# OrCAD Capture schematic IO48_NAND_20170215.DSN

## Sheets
1 01. Title: title: HPS IO48 NAND Daughter Card; rev: A1; note: 150-0330633-A1     (6XX-44480R)
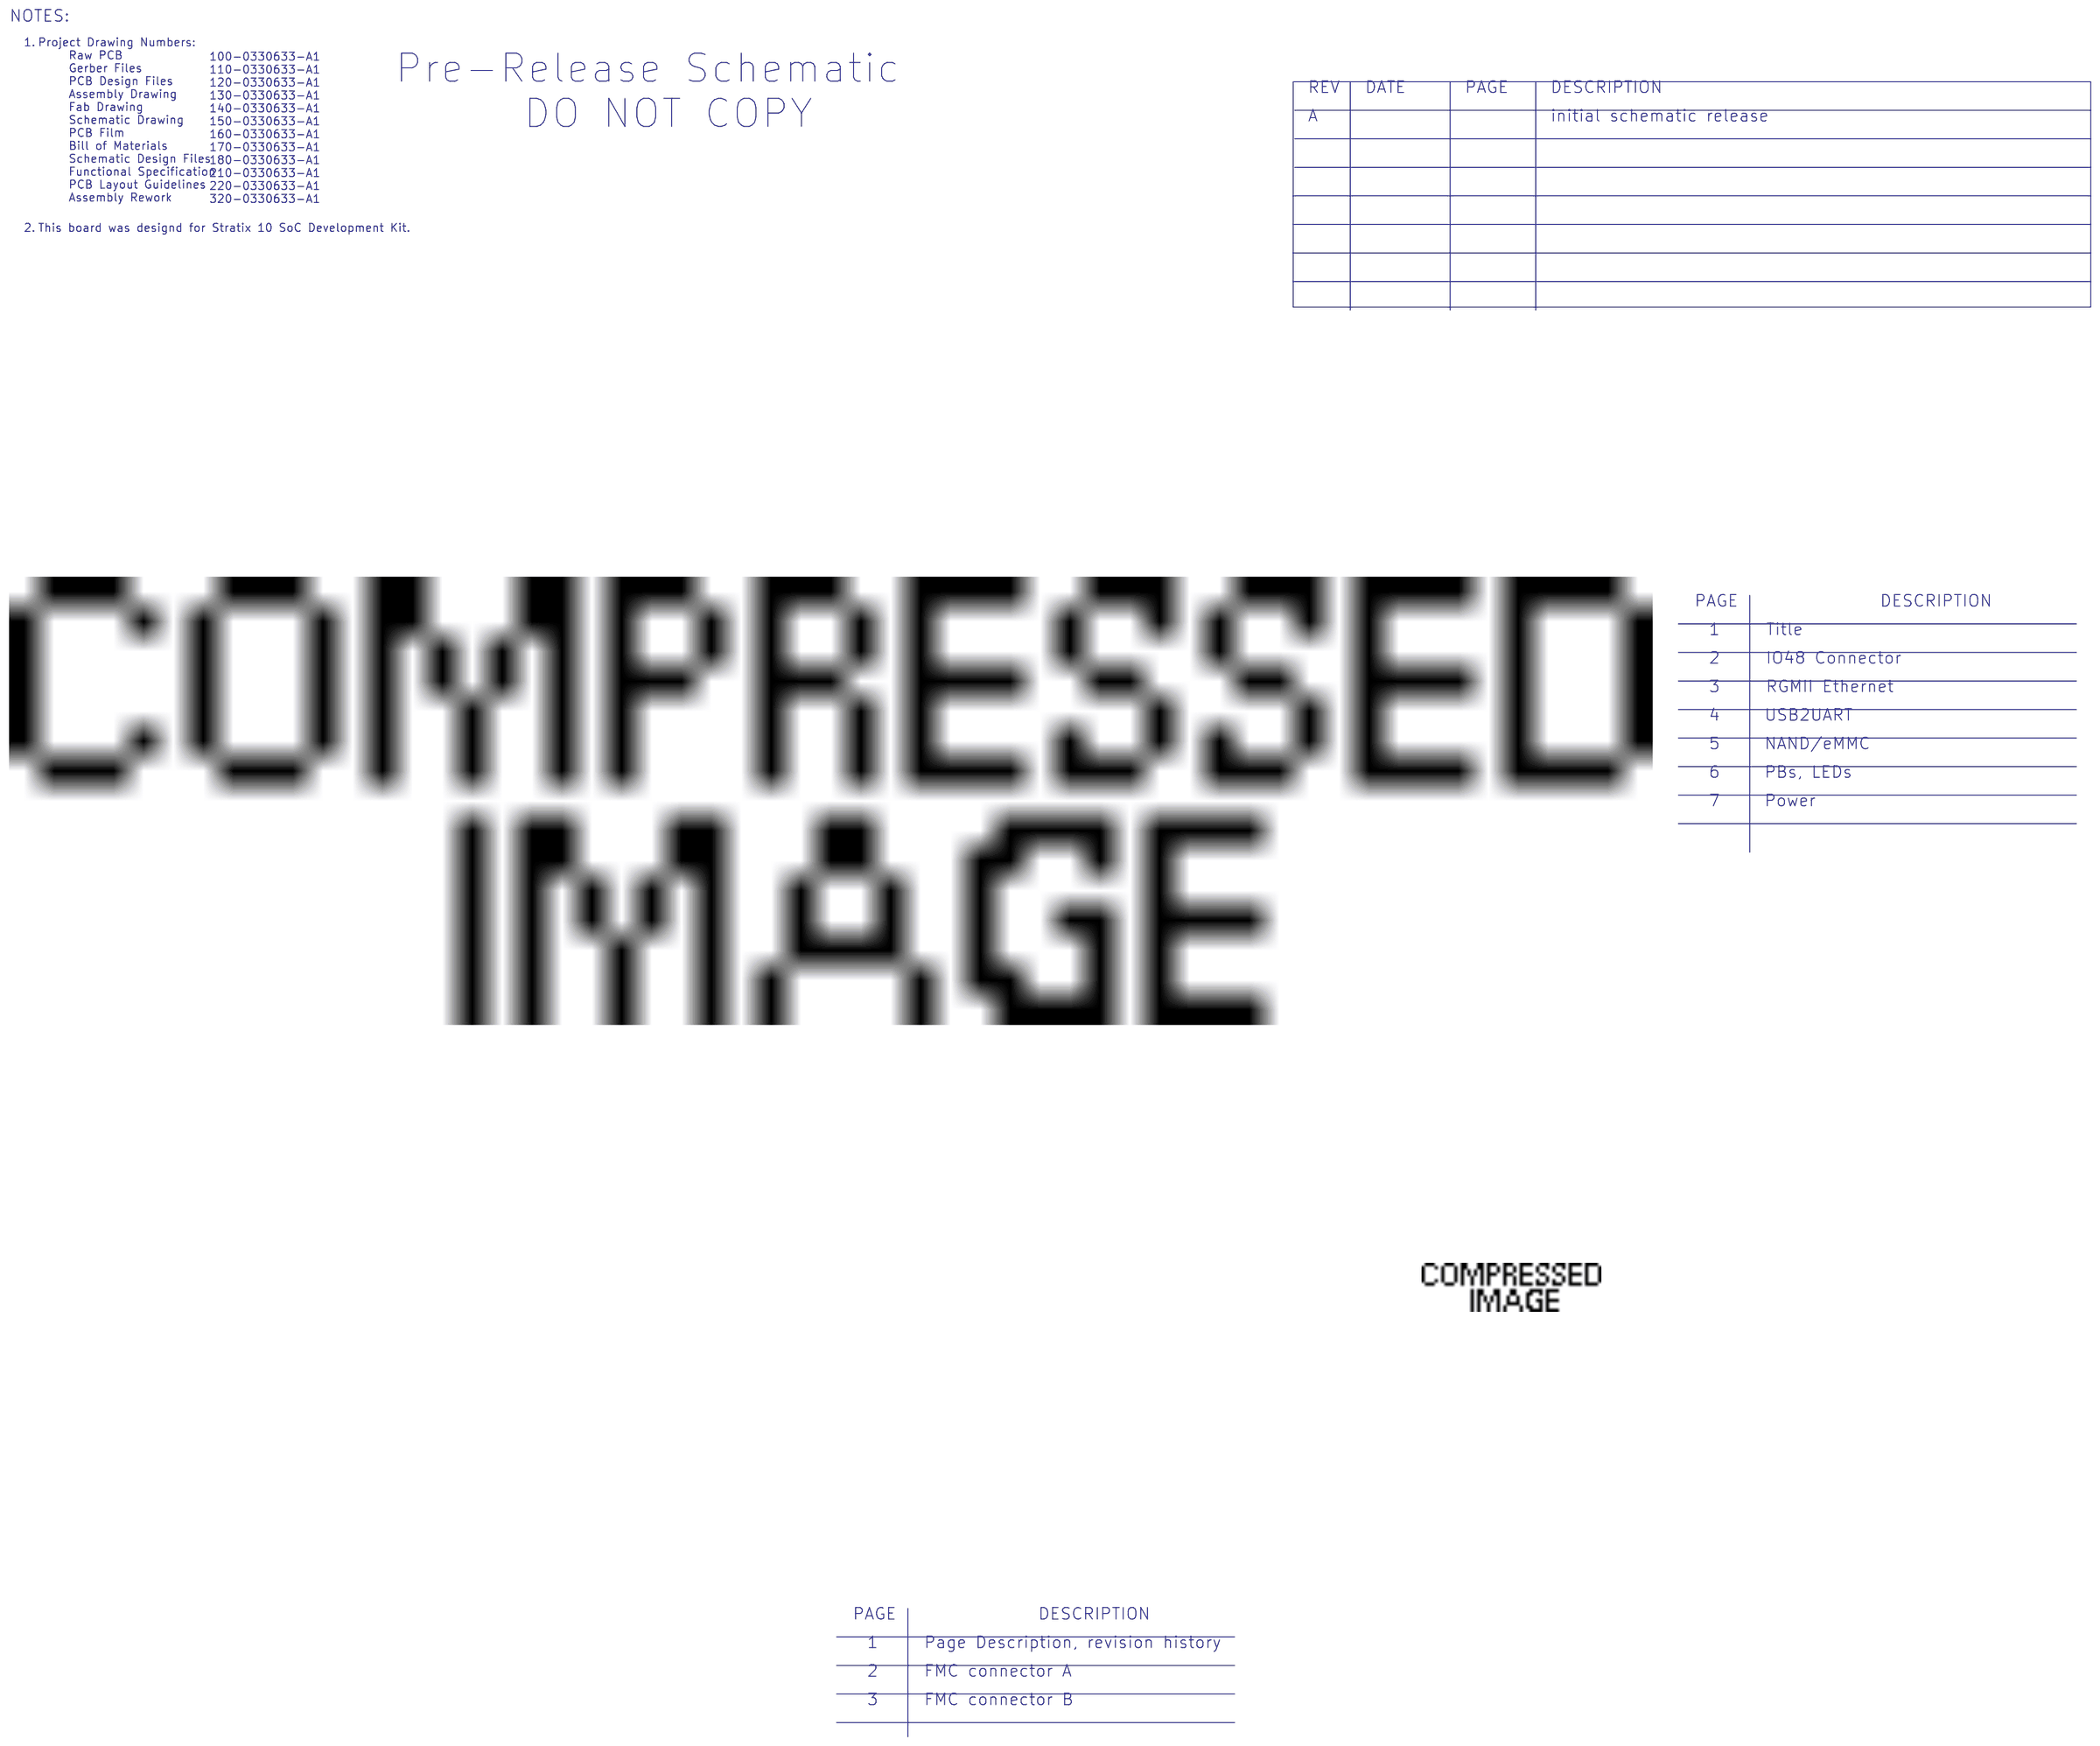
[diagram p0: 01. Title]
2 02. IO48 Connector: size B
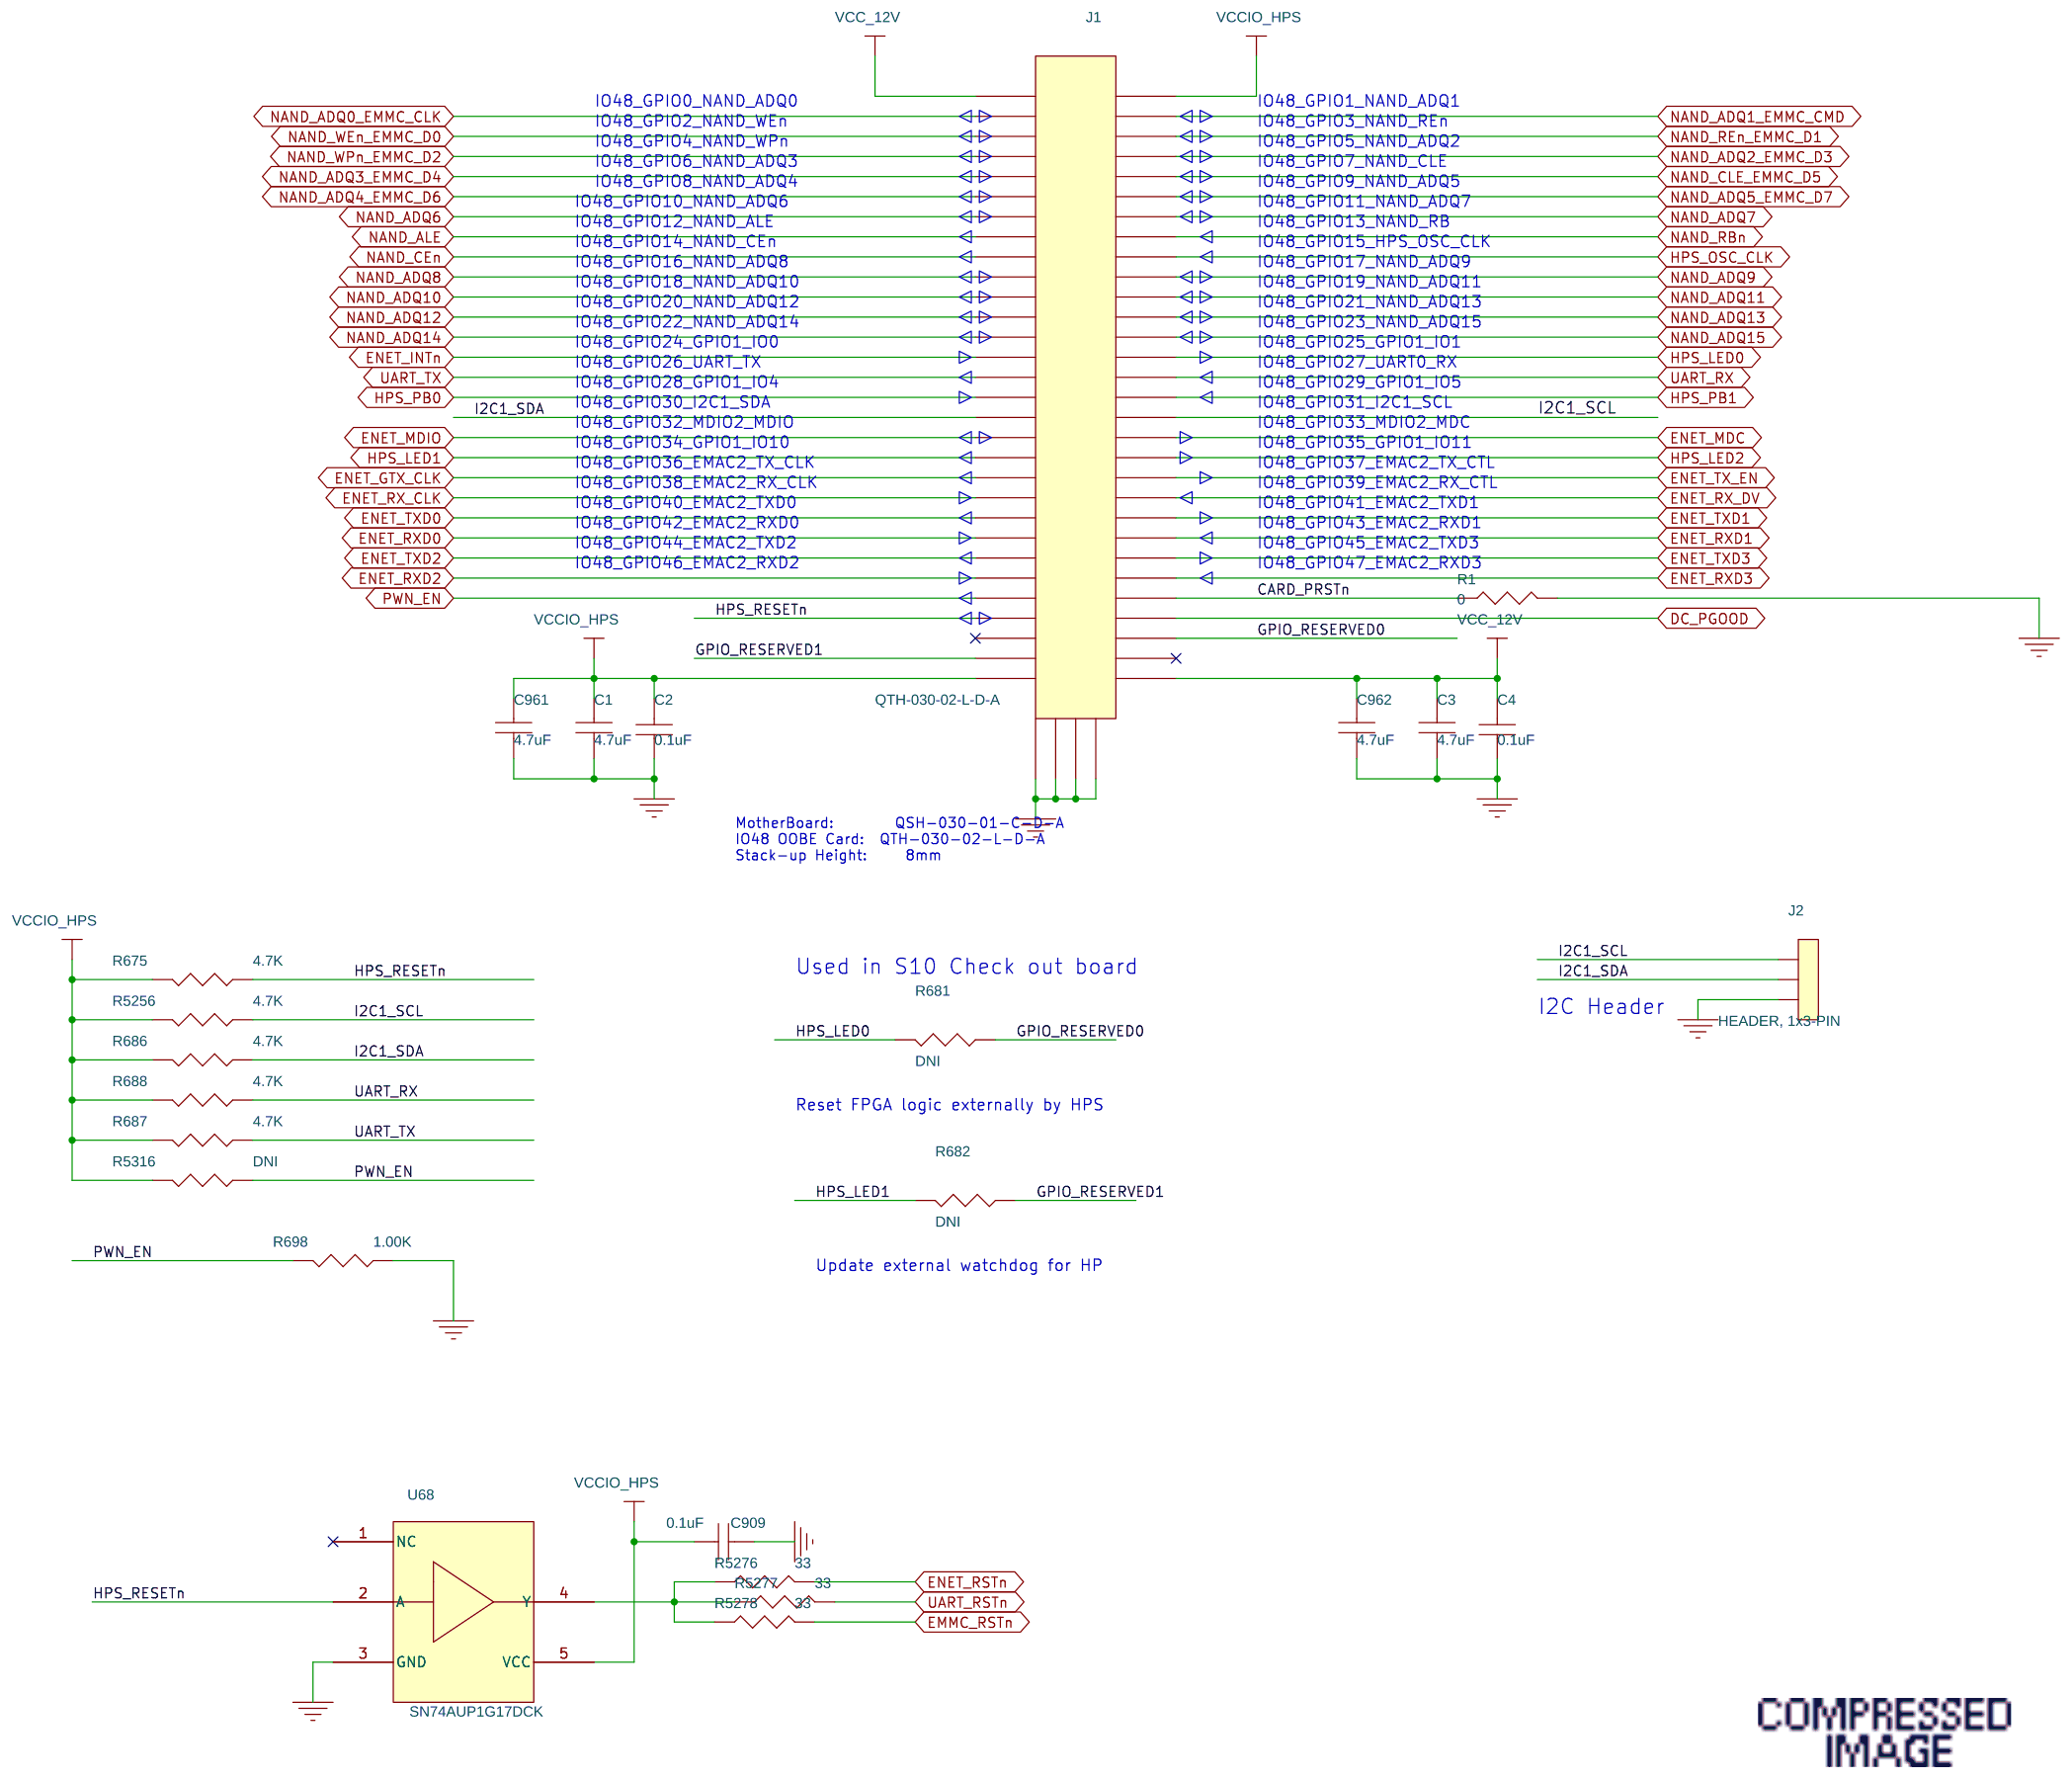
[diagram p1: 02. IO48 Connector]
3 03. RGMII Ethernet: size B
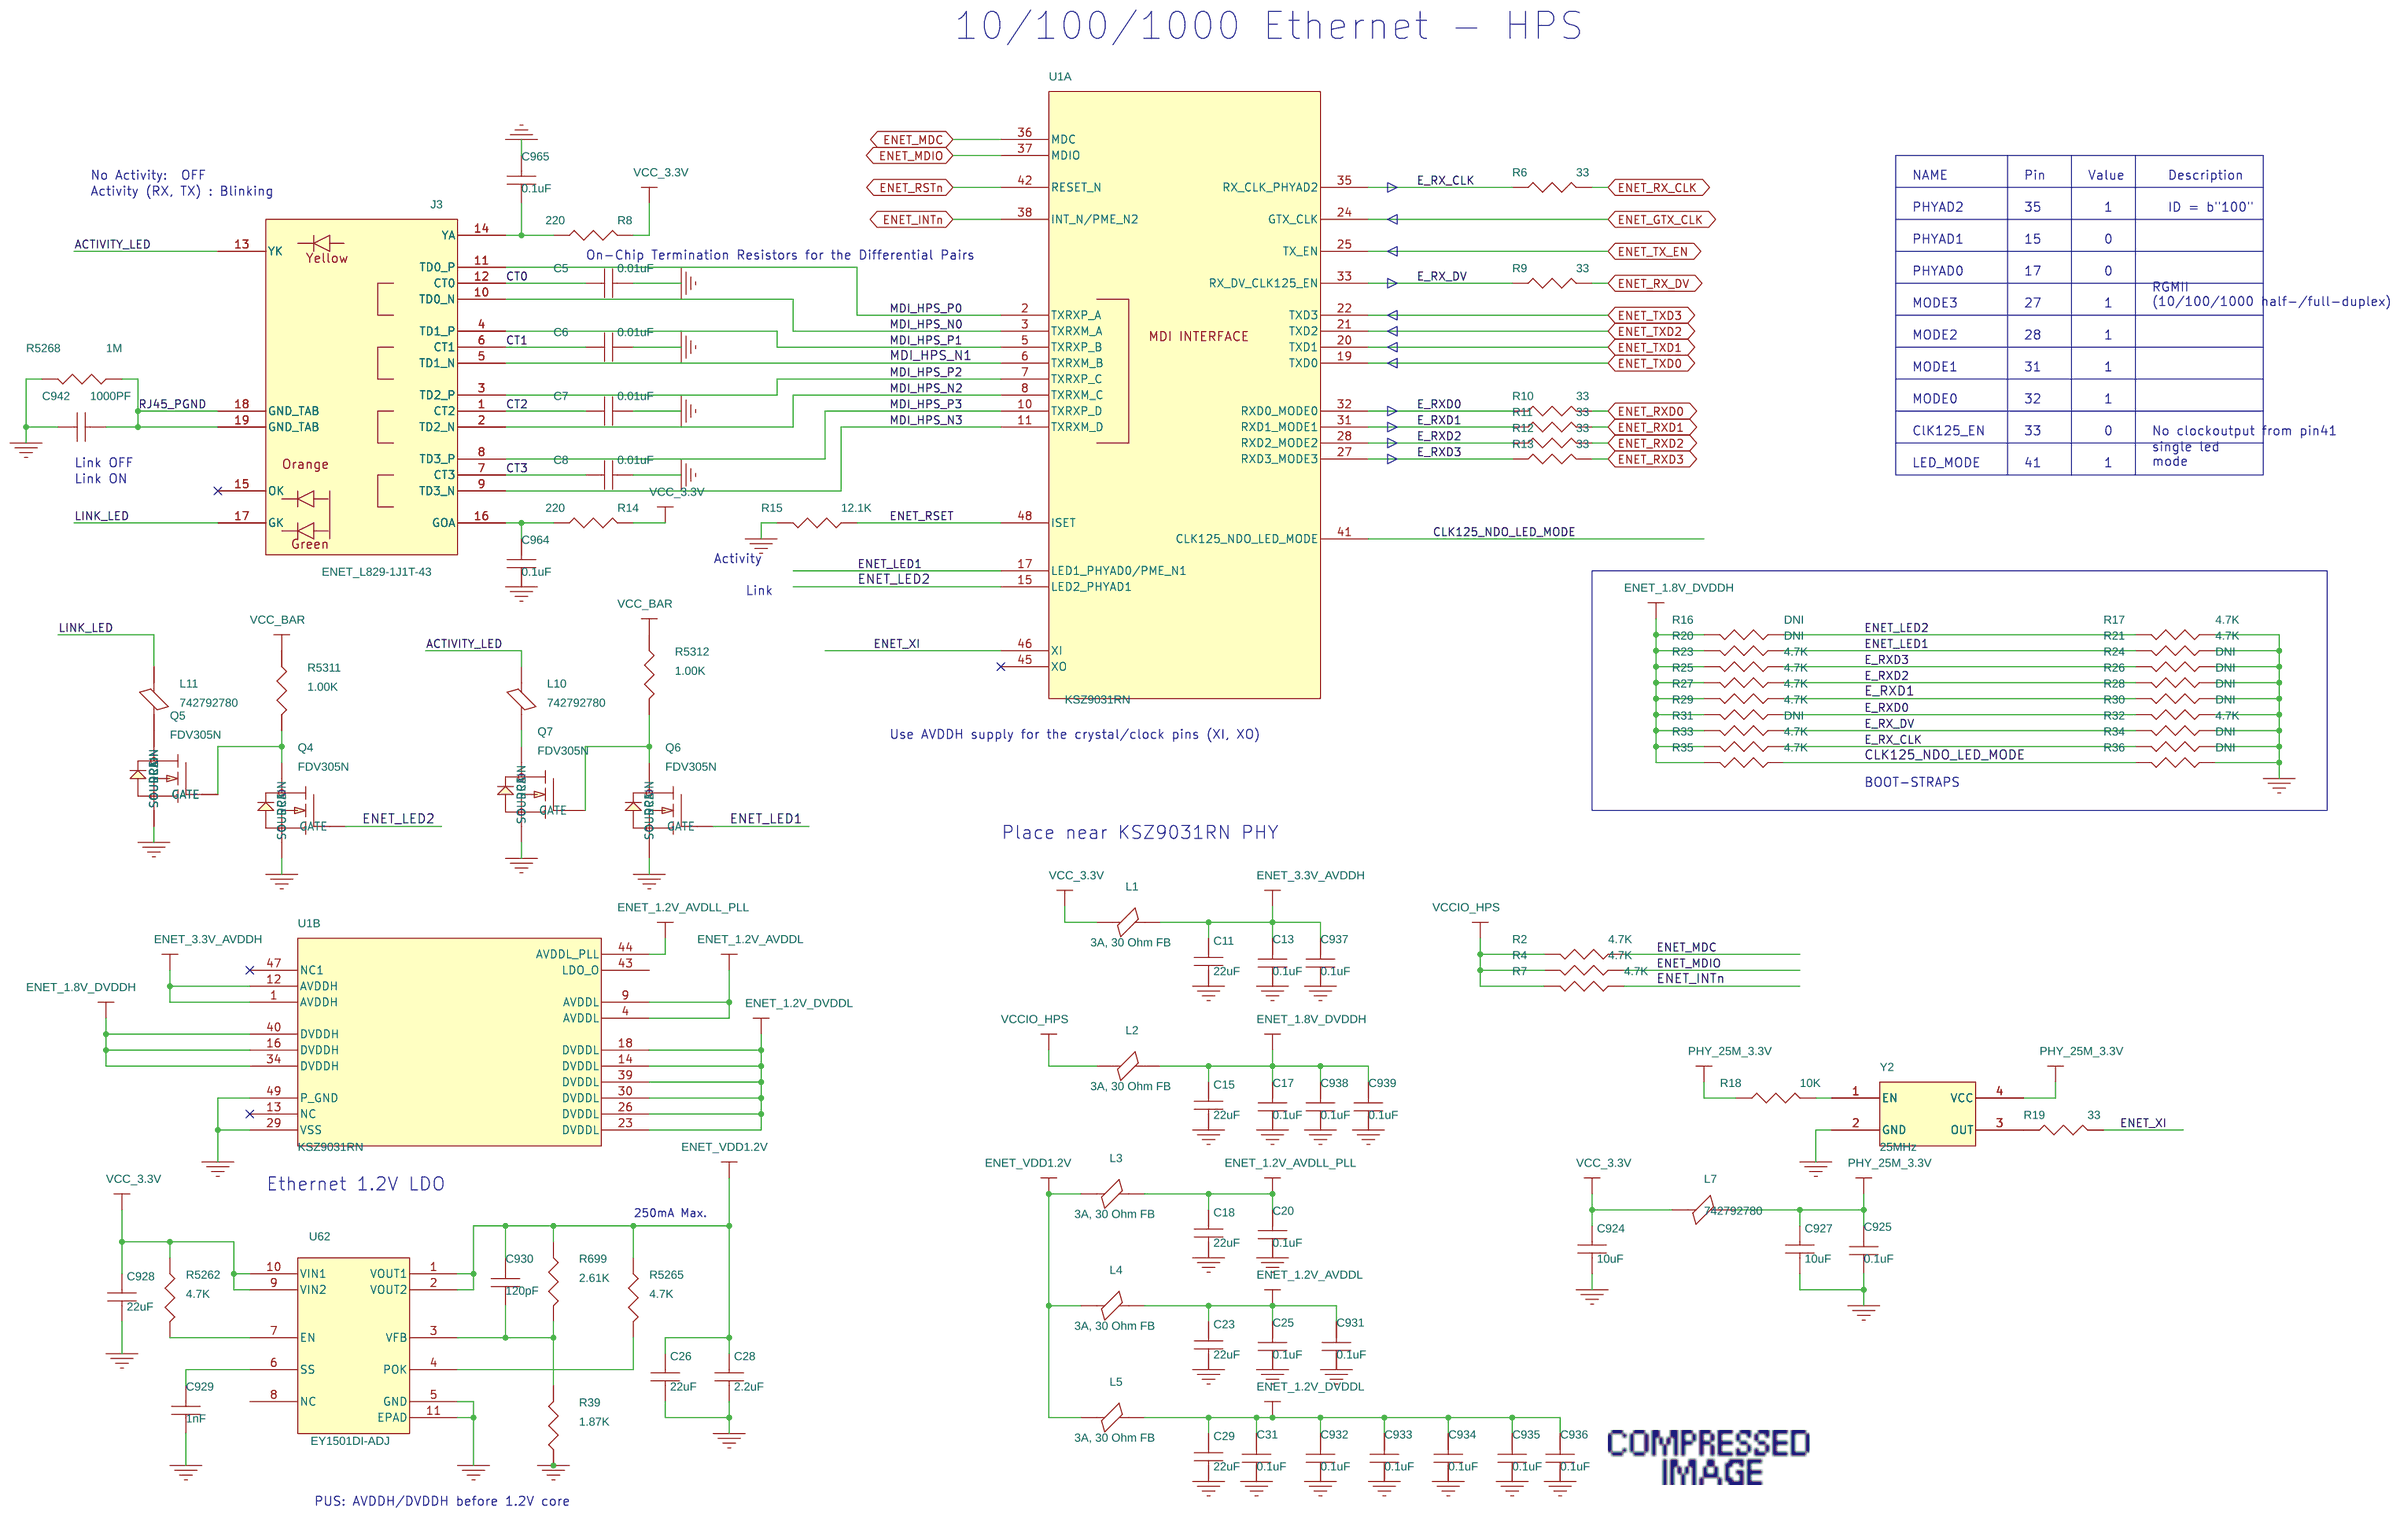
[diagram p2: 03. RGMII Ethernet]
4 04. USB2UART: size B
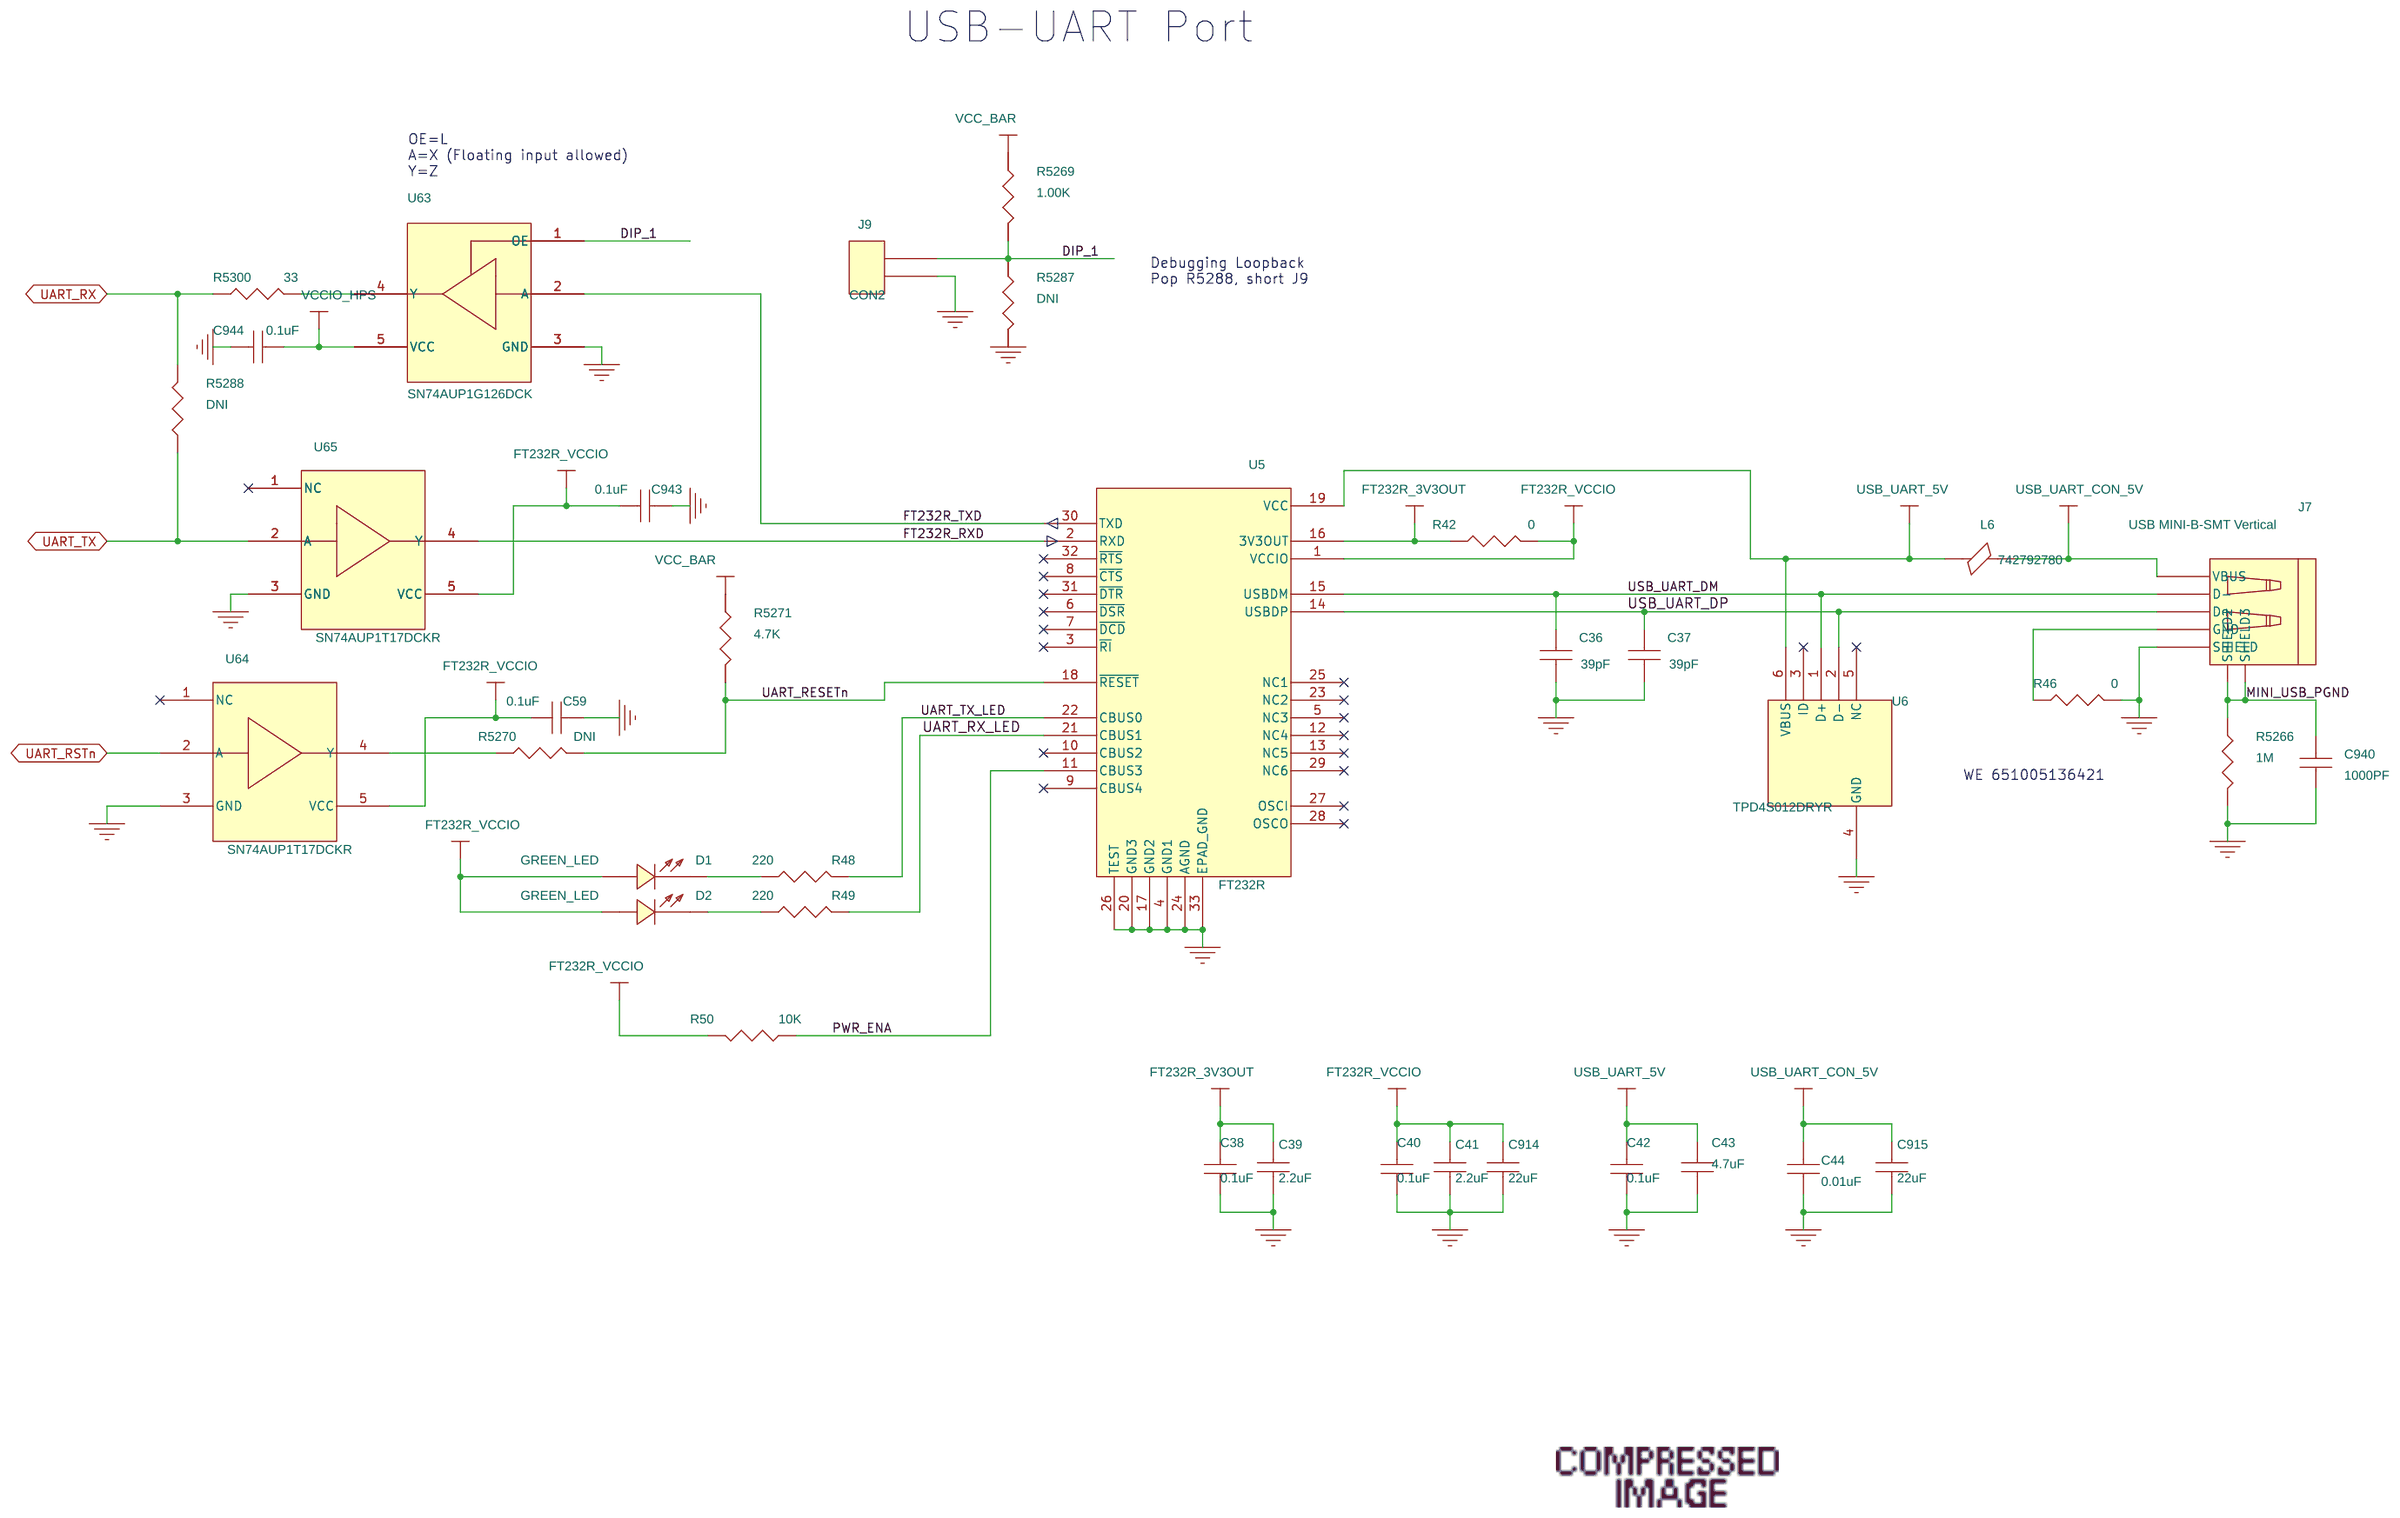
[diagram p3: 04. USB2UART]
5 06. PBs, LEDs: size B
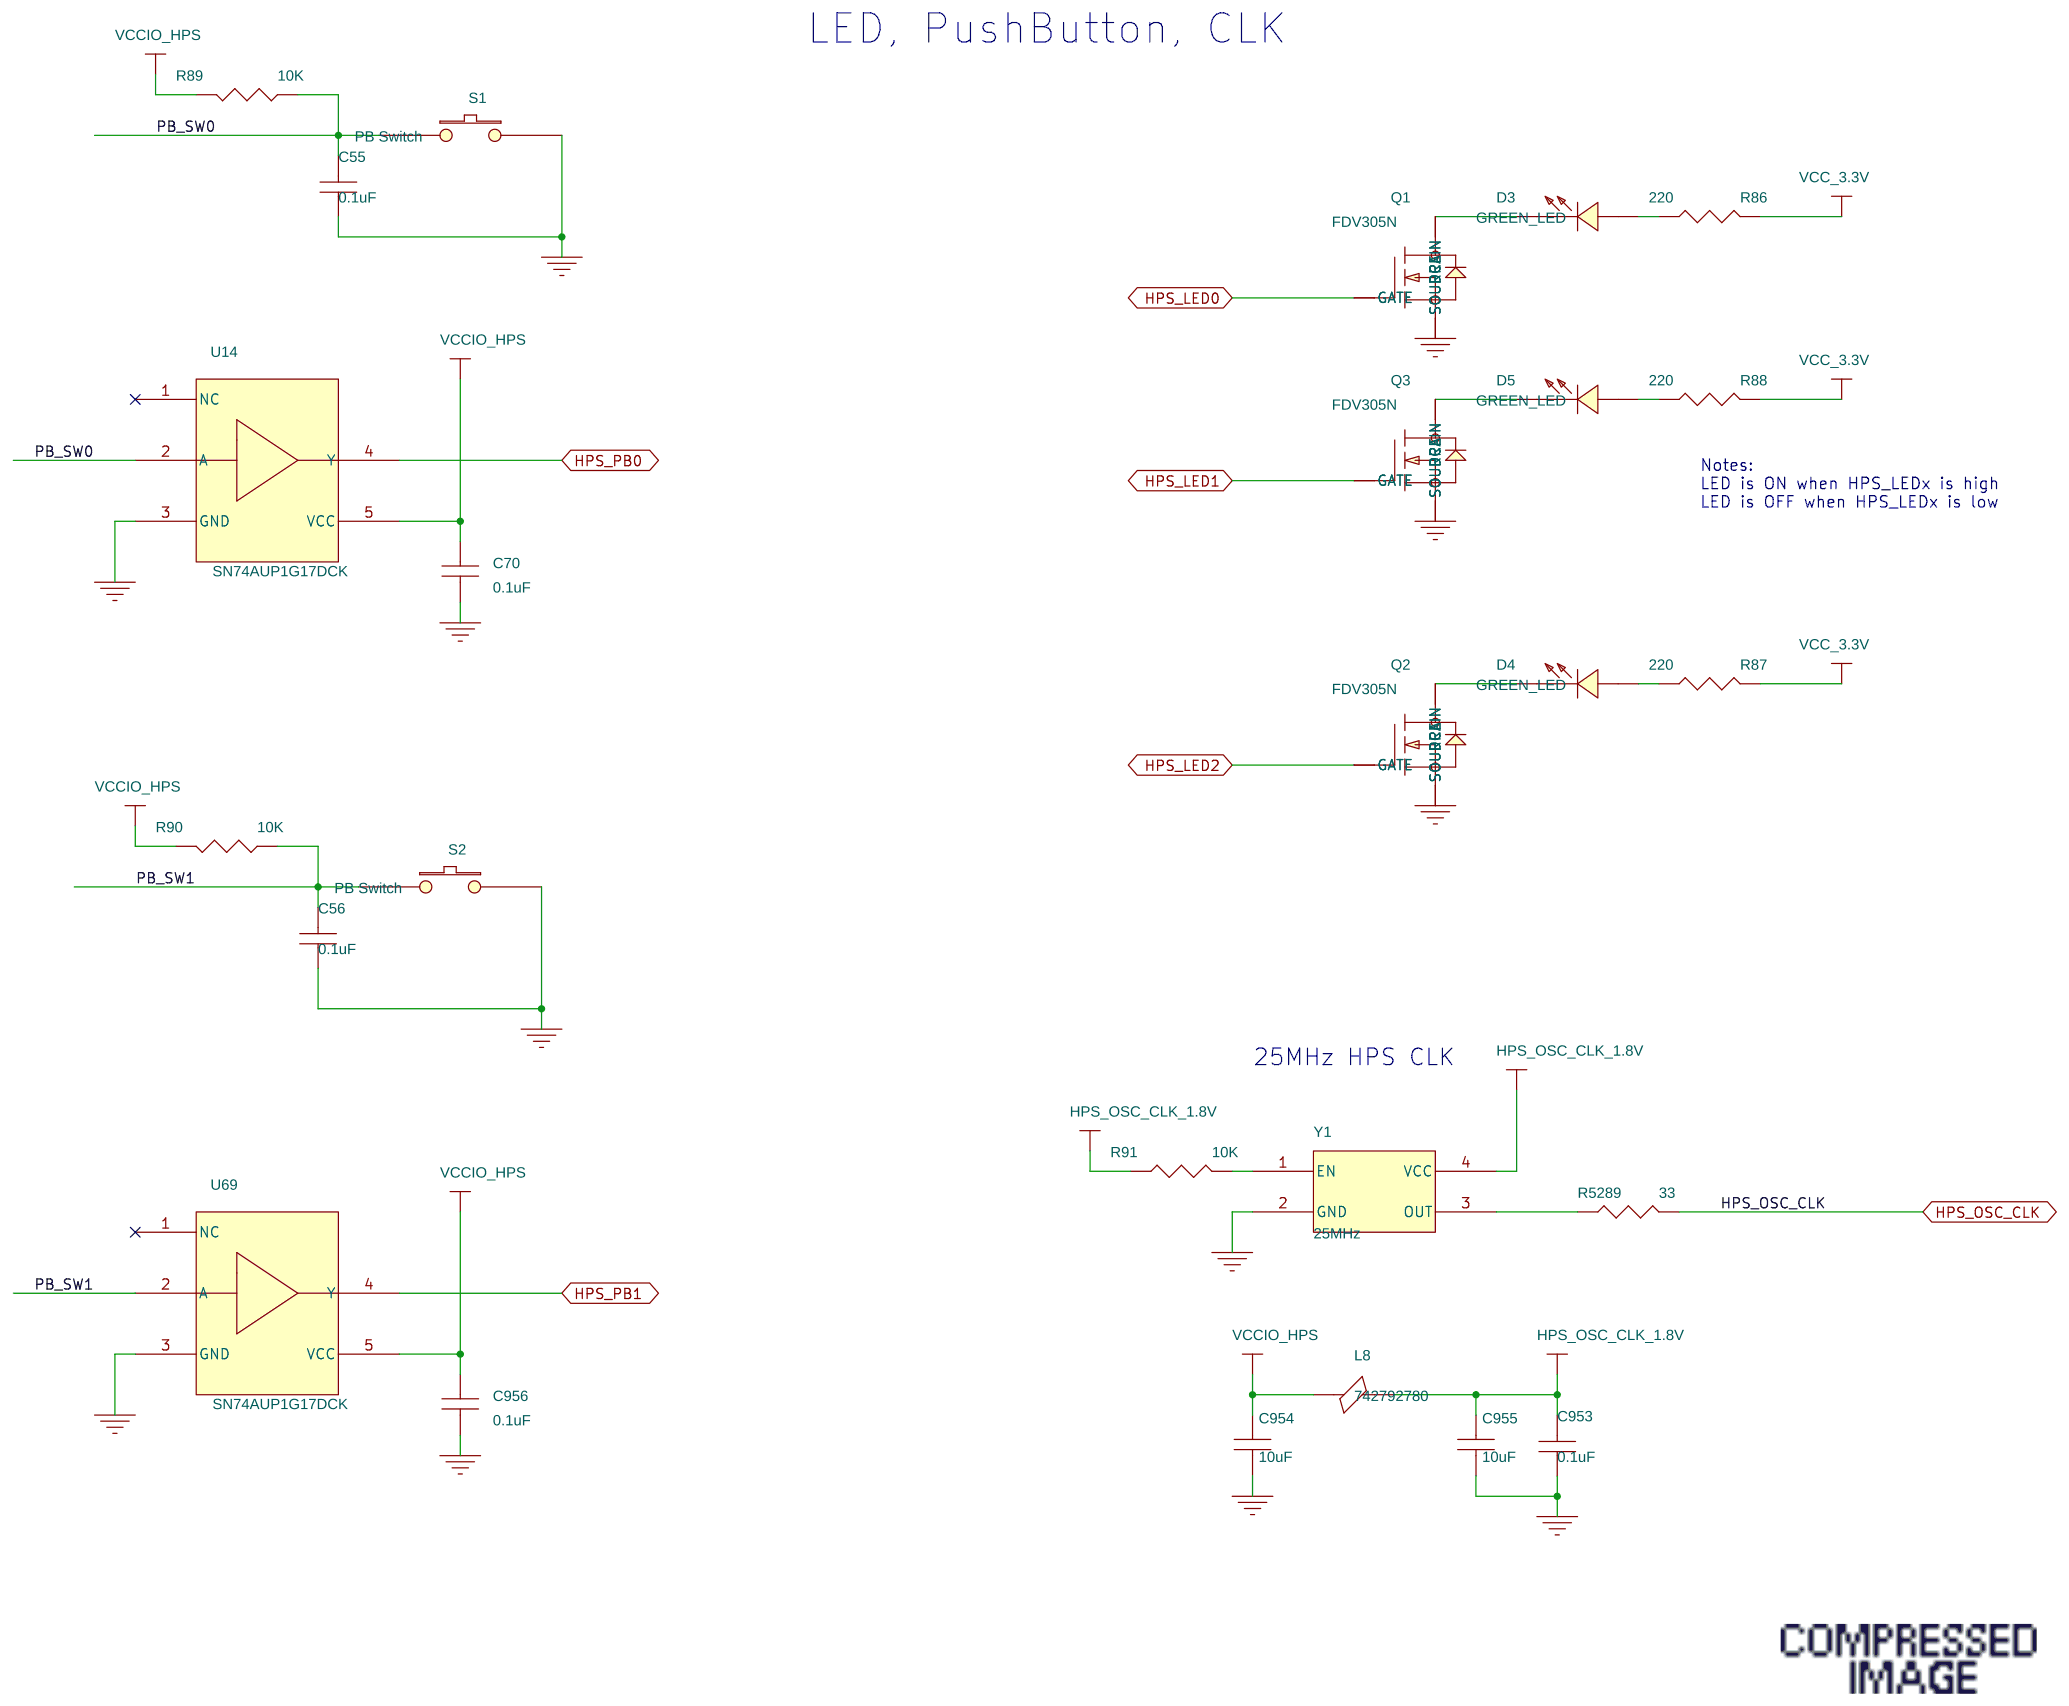
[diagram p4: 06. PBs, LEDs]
6 07. Power: size B
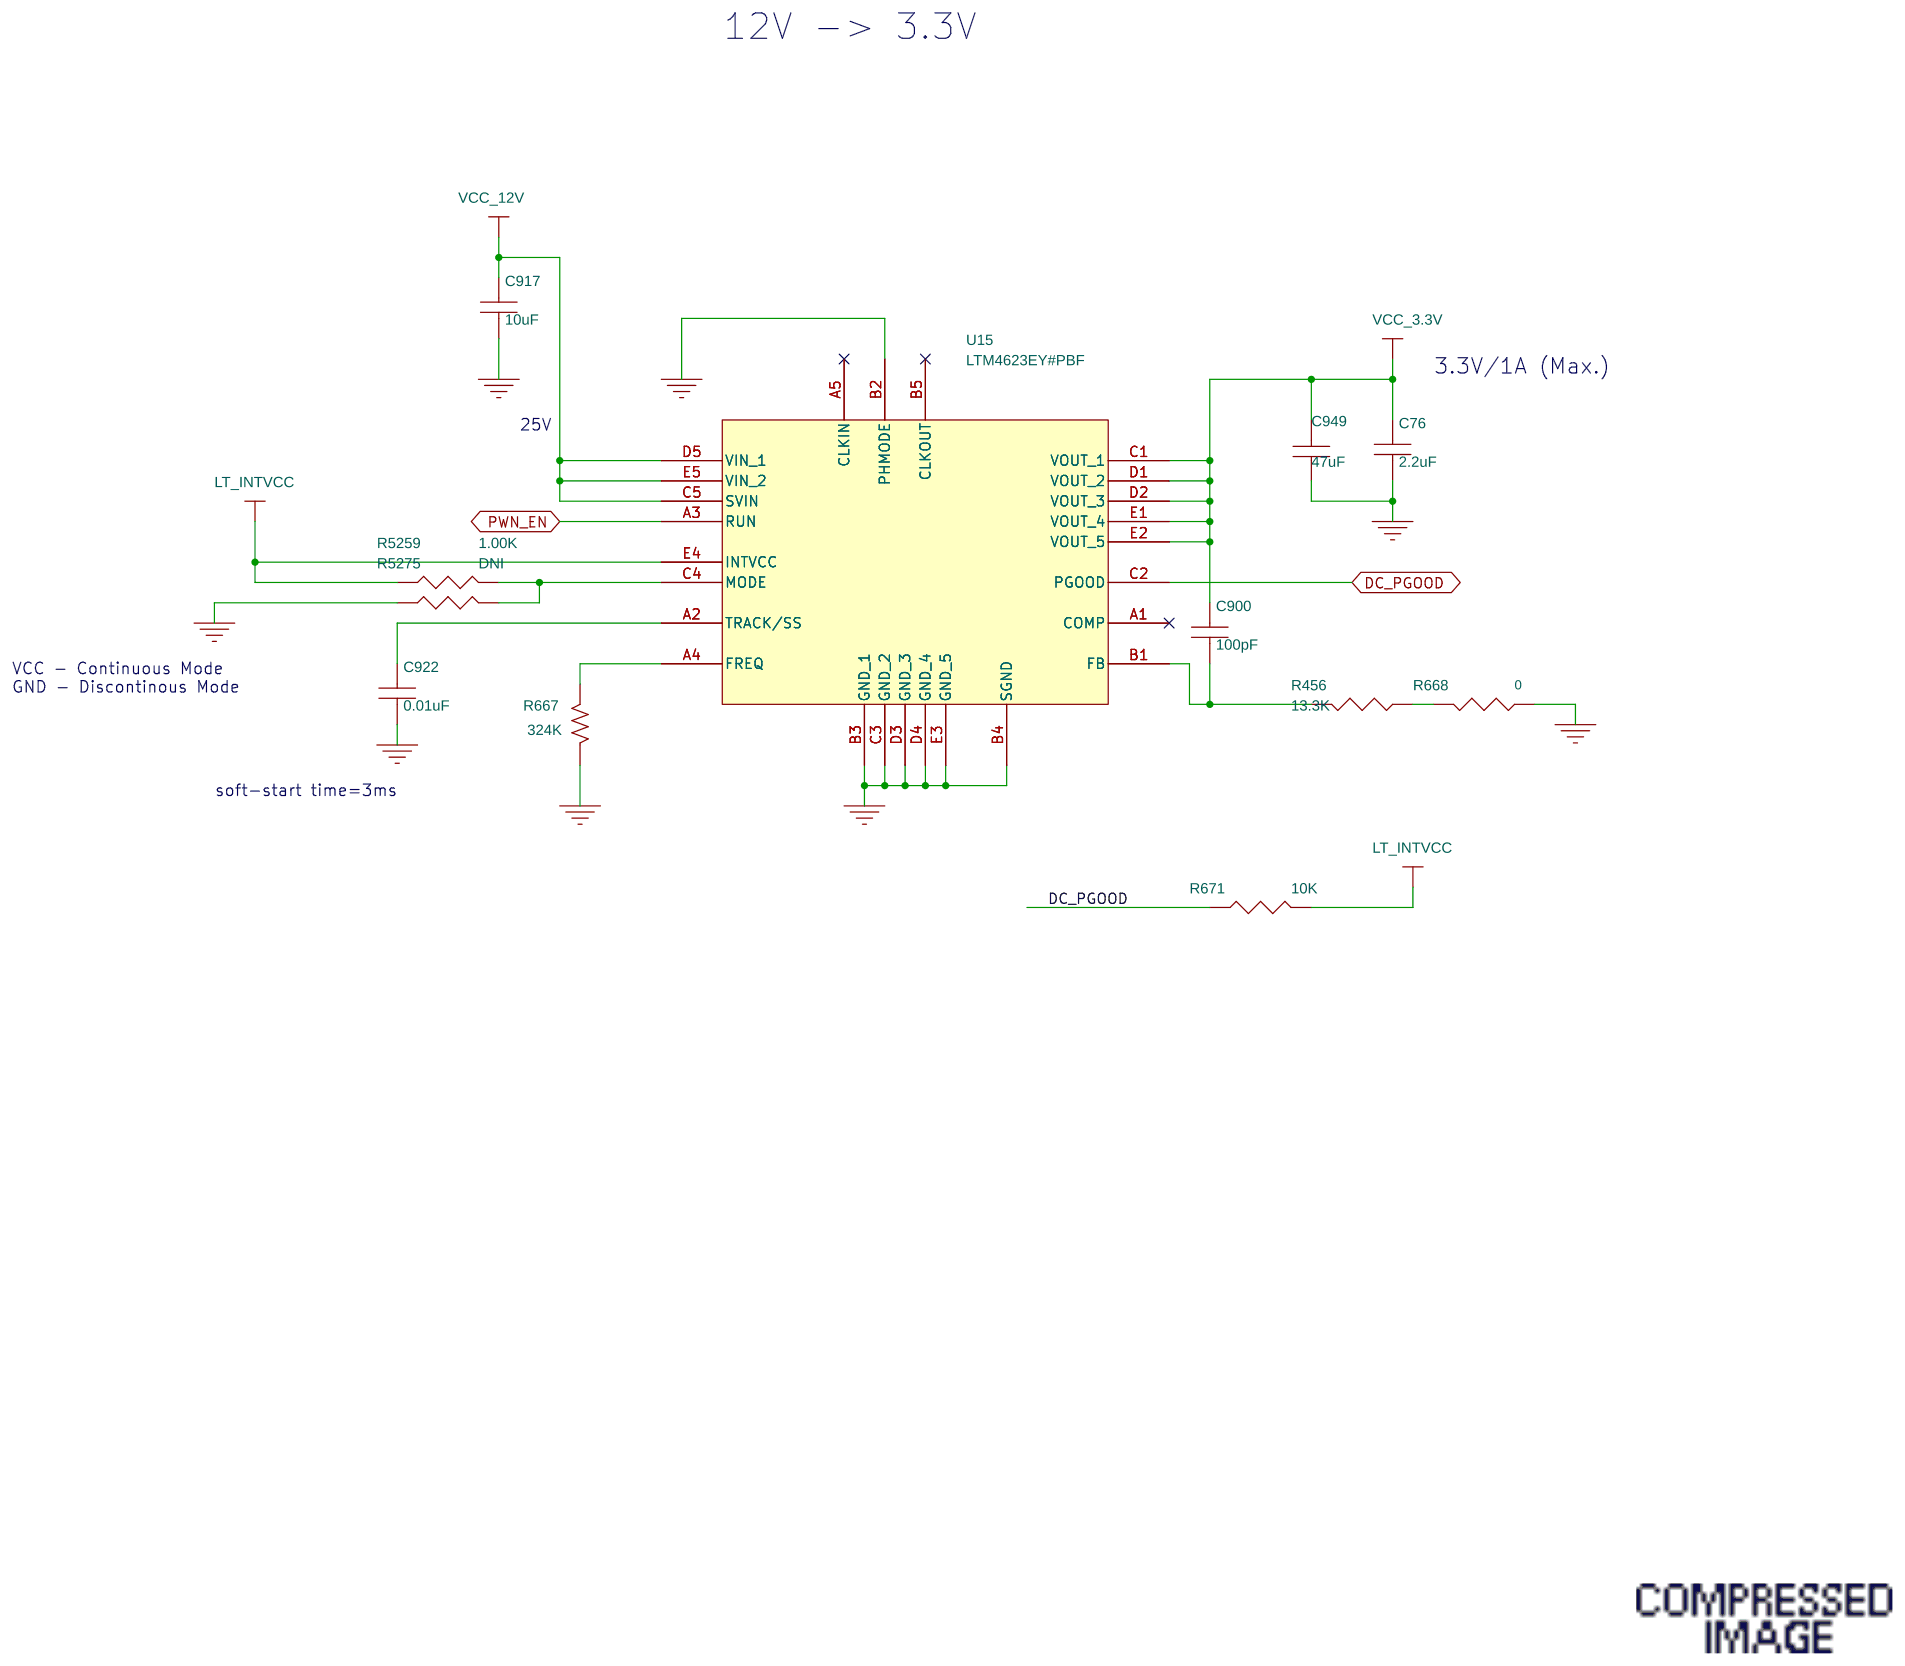
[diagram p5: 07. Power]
7 05. NAND/eMMC: size B
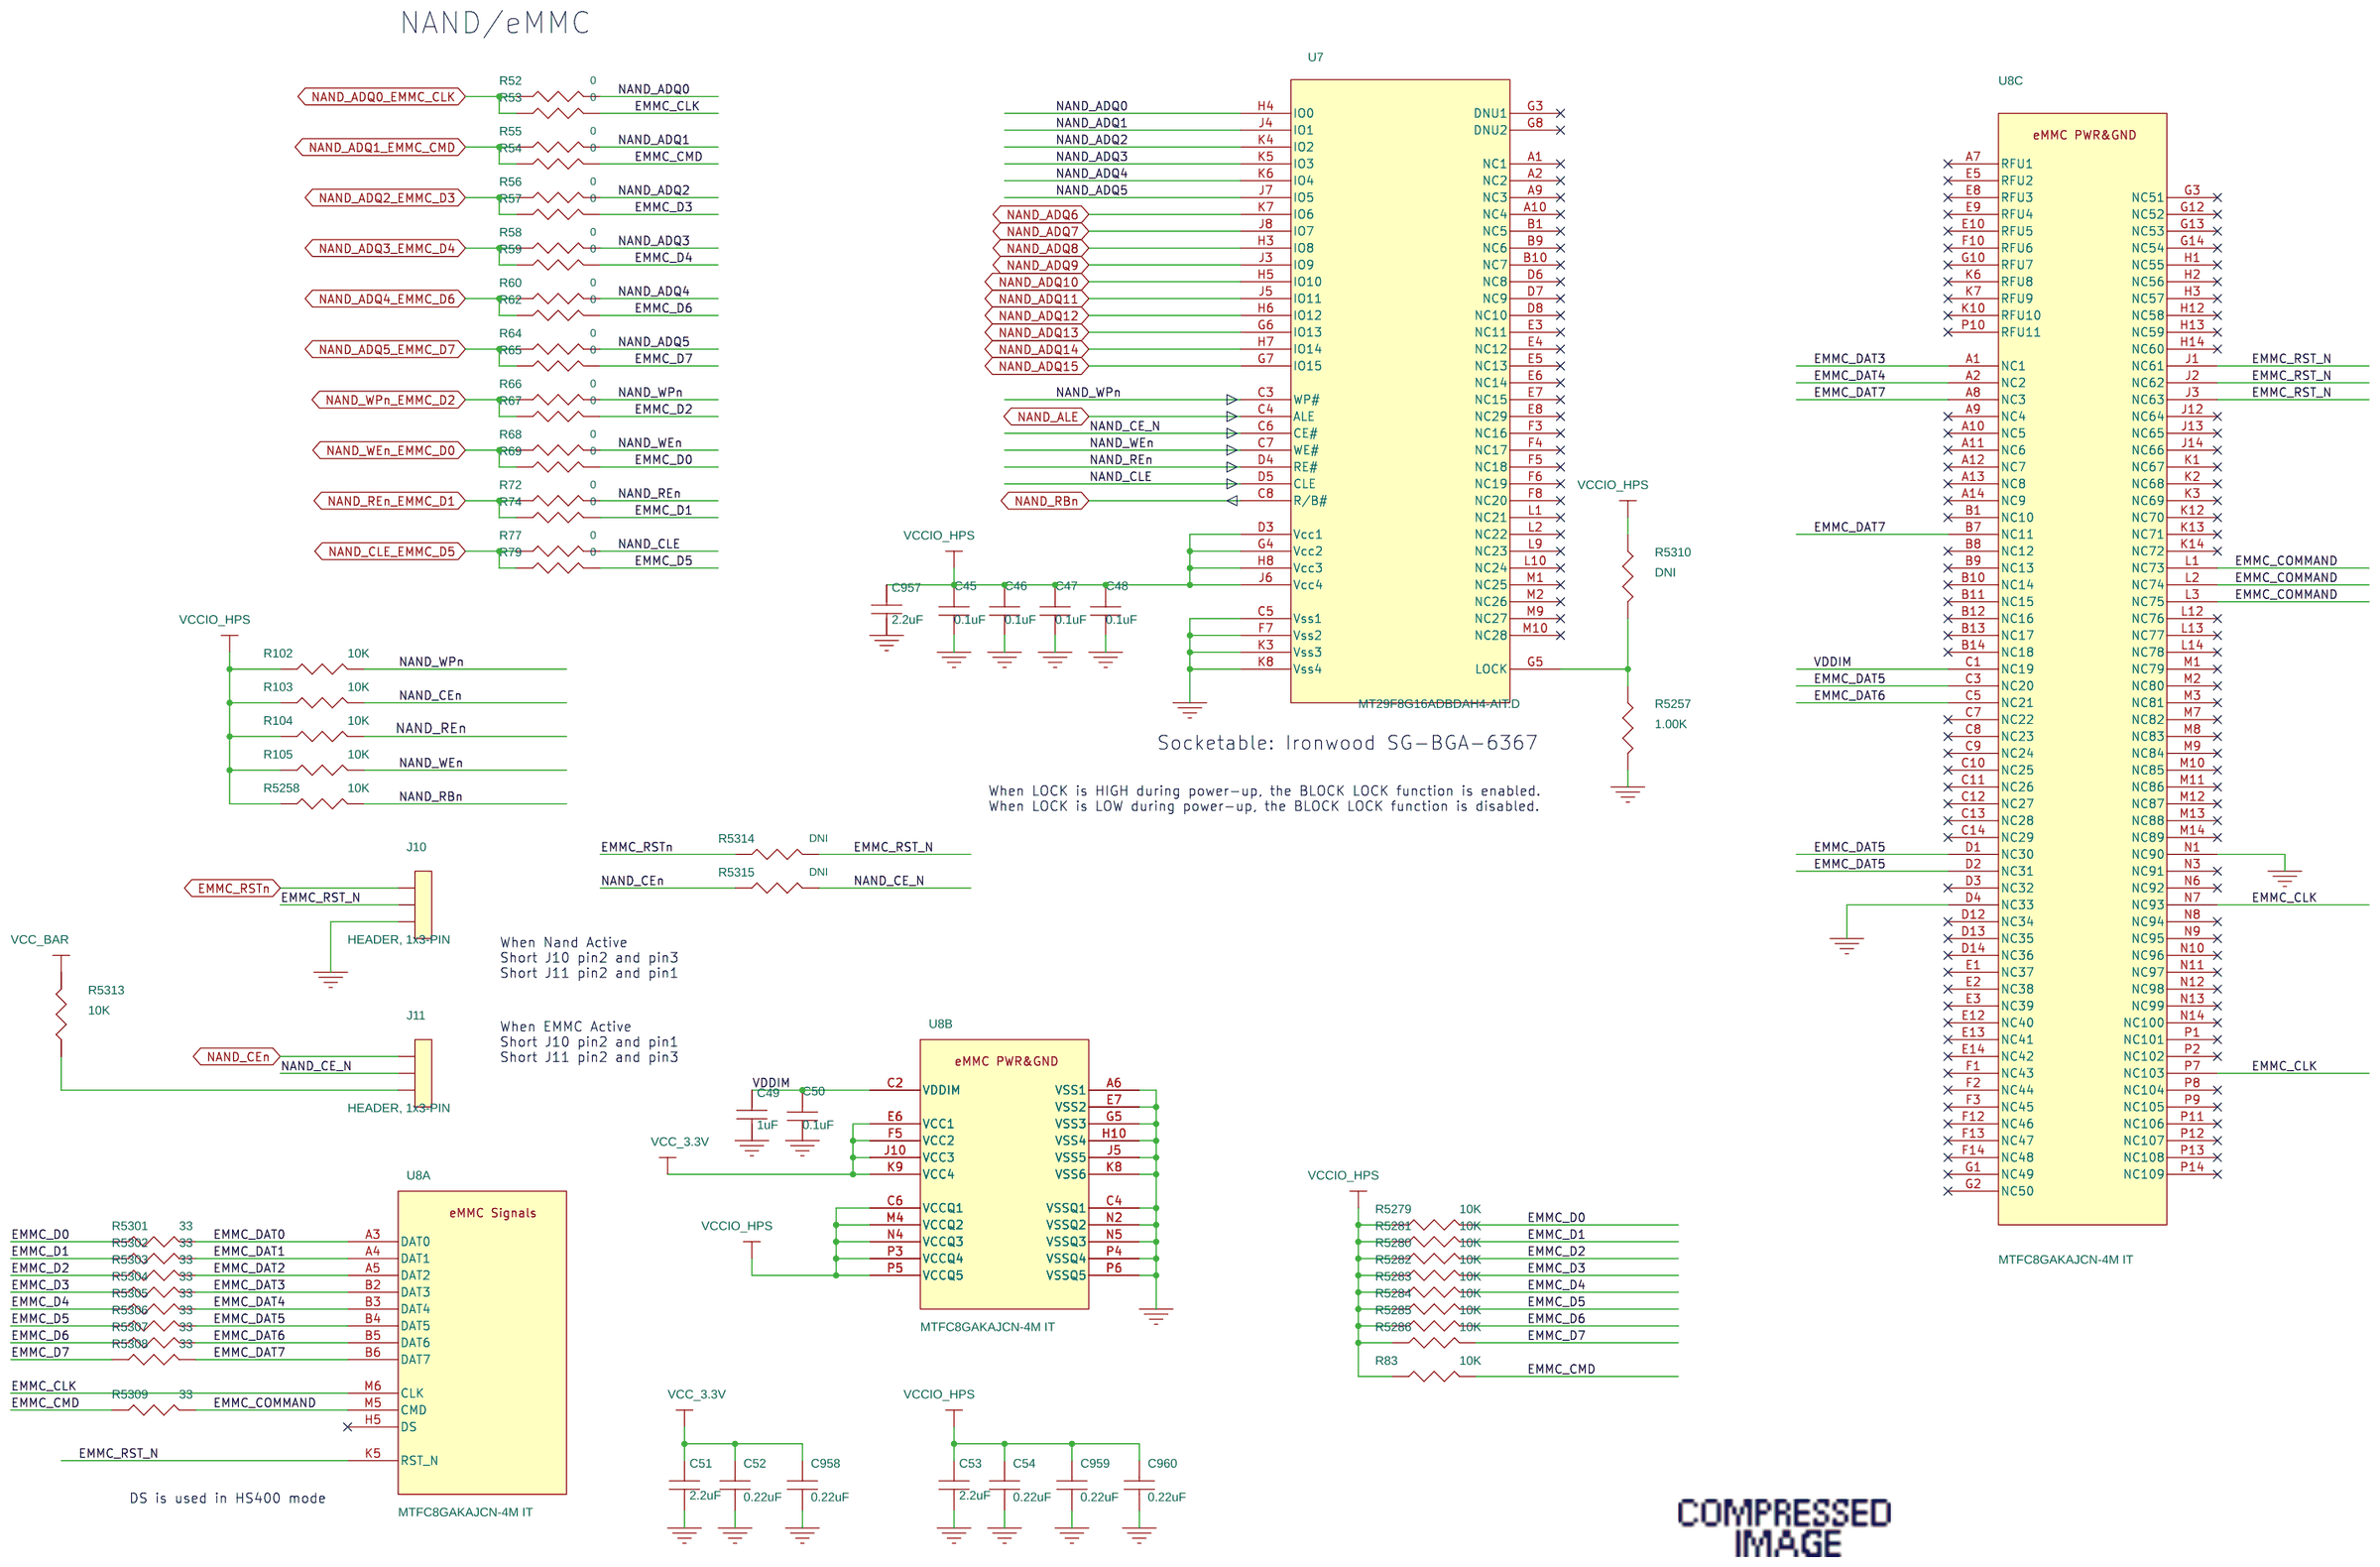
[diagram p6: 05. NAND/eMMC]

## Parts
sheet 02. IO48 Connector
C1  4.7uF  [0805]
C2  0.1uF  [0402]
C3  4.7uF  [0805]
C4  0.1uF  [0402]
C909  0.1uF  [0402]
C961  4.7uF  [0805]
C962  4.7uF  [0805]
J1  QTH-030-02-L-D-A  [QTH-030]
J2  HEADER, 1x3-PIN  [CONN_TSW_103_07_L_S]
R1  0  [0402]
R675  4.7K  [0402]
R681  DNI  [0402]
R682  DNI  [0402]
R686  4.7K  [0402]
R687  4.7K  [0402]
R688  4.7K  [0402]
R698  1.00K  [0402]
R5256  4.7K  [0402]
R5276  33  [0402]
R5277  33  [0402]
R5278  33  [0402]
R5316  DNI  [0402]
U68  SN74AUP1G17DCK  [SC70_TI]
sheet 03. RGMII Ethernet
C5  0.01uF  [0402]
C6  0.01uF  [0402]
C7  0.01uF  [0402]
C8  0.01uF  [0402]
C11  22uF  [0603]
C13  0.1uF  [0402]
C15  22uF  [0603]
C17  0.1uF  [0402]
C18  22uF  [0603]
C20  0.1uF  [0402]
C23  22uF  [0603]
C25  0.1uF  [0402]
C26  22uF  [0603]
C28  2.2uF  [0603]
C29  22uF  [0603]
C31  0.1uF  [0402]
C924  10uF  [C0805]
C925  0.1uF  [0402]
C927  10uF  [C0805]
C928  22uF  [0603]
C929  1nF  [0402]
C930  120pF  [0402]
C931  0.1uF  [0402]
C932  0.1uF  [0402]
C933  0.1uF  [0402]
C934  0.1uF  [0402]
C935  0.1uF  [0402]
C936  0.1uF  [0402]
C937  0.1uF  [0402]
C938  0.1uF  [0402]
C939  0.1uF  [0402]
C942  1000PF  [1808]
C964  0.1uF  [0402]
C965  0.1uF  [0402]
J3  ENET_L829-1J1T-43  [bel_l829-1j1t-43]
L1  3A, 30 Ohm FB  [ind_0603]
L2  3A, 30 Ohm FB  [ind_0603]
L3  3A, 30 Ohm FB  [ind_0603]
L4  3A, 30 Ohm FB  [ind_0603]
L5  3A, 30 Ohm FB  [ind_0603]
L7  742792780  [0402]
L10  742792780  [0402]
L11  742792780  [0402]
Q4  FDV305N  [SOT23]
Q5  FDV305N  [SOT23]
Q6  FDV305N  [SOT23]
Q7  FDV305N  [SOT23]
R2  4.7K  [0402]
R4  4.7K  [0402]
R6  33  [0402]
R7  4.7K  [0402]
R8  220  [0402]
R9  33  [0402]
R10  33  [0402]
R11  33  [0402]
R12  33  [0402]
R13  33  [0402]
R14  220  [0402]
R15  12.1K  [0402]
R16  DNI  [0402]
R17  4.7K  [0402]
R18  10K  [0402]
R19  33  [0402]
R20  DNI  [0402]
R21  4.7K  [0402]
R23  4.7K  [0402]
R24  DNI  [0402]
R25  4.7K  [0402]
R26  DNI  [0402]
R27  4.7K  [0402]
R28  DNI  [0402]
R29  4.7K  [0402]
R30  DNI  [0402]
R31  DNI  [0402]
R32  4.7K  [0402]
R33  4.7K  [0402]
R34  DNI  [0402]
R35  4.7K  [0402]
R36  DNI  [0402]
R39  1.87K  [0402]
R699  2.61K  [0402]
R5262  4.7K  [0402]
R5265  4.7K  [0402]
R5268  1M  [1206]
R5311  1.00K  [0402]
R5312  1.00K  [0402]
U1  KSZ9031RN  [QFN48]  (sections A,B)
U62  EY1501DI-ADJ  [DFN-10]
Y2  25MHz  [OSC7050]
sheet 04. USB2UART
C36  39pF  [0402]
C37  39pF  [0402]
C38  0.1uF  [0402]
C39  2.2uF  [0603]
C40  0.1uF  [0402]
C41  2.2uF  [0603]
C42  0.1uF  [0402]
C43  4.7uF  [0805]
C44  0.01uF  [0402]
C59  0.1uF  [0402]
C914  22uF  [0603]
C915  22uF  [0603]
C940  1000PF  [1808]
C943  0.1uF  [0402]
C944  0.1uF  [0402]
D1  GREEN_LED  [LED_0603]
D2  GREEN_LED  [LED_0603]
J7  USB MINI-B-SMT Vertical  [MINI_USB_SMTB]
J9  CON2  [HDR2x1_100MIL]
L6  742792780  [0402]
R42  0  [0402]
R46  0  [0402]
R48  220  [0402]
R49  220  [0402]
R50  10K  [0402]
R5266  1M  [1206]
R5269  1.00K  [0402]
R5270  DNI  [0402]
R5271  4.7K  [0402]
R5287  DNI  [0402]
R5288  DNI  [0402]
R5300  33  [0402]
U5  FT232R  [Qfn32-ftdi]
U6  TPD4S012DRYR  [SON6]
U63  SN74AUP1G126DCK  [SC70_TI]
U64  SN74AUP1T17DCKR  [SC70_TI]
U65  SN74AUP1T17DCKR  [SC70_TI]
sheet 05. NAND/eMMC
C45  0.1uF  [0402]
C46  0.1uF  [0402]
C47  0.1uF  [0402]
C48  0.1uF  [0402]
C49  1uF  [0603]
C50  0.1uF  [0402]
C51  2.2uF  [0603]
C52  0.22uF  [0402]
C53  2.2uF  [0603]
C54  0.22uF  [0402]
C957  2.2uF  [0603]
C958  0.22uF  [0402]
C959  0.22uF  [0402]
C960  0.22uF  [0402]
J10  HEADER, 1x3-PIN  [CONN_TSW_103_07_L_S]
J11  HEADER, 1x3-PIN  [CONN_TSW_103_07_L_S]
R52  0  [0402]
R53  0  [0402]
R54  0  [0402]
R55  0  [0402]
R56  0  [0402]
R57  0  [0402]
R58  0  [0402]
R59  0  [0402]
R60  0  [0402]
R62  0  [0402]
R64  0  [0402]
R65  0  [0402]
R66  0  [0402]
R67  0  [0402]
R68  0  [0402]
R69  0  [0402]
R72  0  [0402]
R74  0  [0402]
R77  0  [0402]
R79  0  [0402]
R83  10K  [0402]
R102  10K  [0402]
R103  10K  [0402]
R104  10K  [0402]
R105  10K  [0402]
R5257  1.00K  [0402]
R5258  10K  [0402]
R5279  10K  [0402]
R5280  10K  [0402]
R5281  10K  [0402]
R5282  10K  [0402]
R5283  10K  [0402]
R5284  10K  [0402]
R5285  10K  [0402]
R5286  10K  [0402]
R5301  33  [0402]
R5302  33  [0402]
R5303  33  [0402]
R5304  33  [0402]
R5305  33  [0402]
R5306  33  [0402]
R5307  33  [0402]
R5308  33  [0402]
R5309  33  [0402]
R5310  DNI  [0402]
R5313  10K  [0402]
R5314  DNI  [0402]
R5315  DNI  [0402]
U7  MT29F8G16ADBDAH4-AIT:D  [VFBGA63_Socket]
U8  MTFC8GAKAJCN-4M IT  [VFBGA-153]  (sections A,B,C)
sheet 06. PBs, LEDs
C55  0.1uF  [0402]
C56  0.1uF  [0402]
C70  0.1uF  [0402]
C953  0.1uF  [0402]
C954  10uF  [C0805]
C955  10uF  [C0805]
C956  0.1uF  [0402]
D3  GREEN_LED  [LED_0603]
D4  GREEN_LED  [LED_0603]
D5  GREEN_LED  [LED_0603]
L8  742792780  [0402]
Q1  FDV305N  [SOT23]
Q2  FDV305N  [SOT23]
Q3  FDV305N  [SOT23]
R86  220  [0402]
R87  220  [0402]
R88  220  [0402]
R89  10K  [0402]
R90  10K  [0402]
R91  10K  [0402]
R5289  33  [0402]
S1  PB Switch  [WURTH_6X3P5_TACT_SWITCH]
S2  PB Switch  [WURTH_6X3P5_TACT_SWITCH]
U14  SN74AUP1G17DCK  [SC70_TI]
U69  SN74AUP1G17DCK  [SC70_TI]
Y1  25MHz  [OSC3250]
sheet 07. Power
C76  2.2uF  [0603]
C900  100pF  [0402]
C917  10uF  [1206]
C922  0.01uF  [0402]
C949  47uF  [1206]
R456  13.3K  [0402]
R667  324K  [R0402]
R668  0  [0402]
R671  10K  [0402]
R5259  1.00K  [0402]
R5275  DNI  [0402]
U15  LTM4623EY#PBF  [BGA25]

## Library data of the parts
C1 C3 C43 C961 C962 = CAP: CAP - CER, 4.7UF, 16V, X5R, 0805; Item Num: P03-15412R; Manufacturer: Murata; Manufacturer Part Num: GRM21BR61C475KA88L; Num Pins: 2; RoHS Compliant: RoHS Compliant
C2 C4 C13 C17 C20 C25 C31 C50 C55 C56 C925 C931-C939 C953 C964 C965 = CAP: CAP CER 0.1UF 25V 20% X7R 0402; Item Num: P03-17618R; LIFECYCLE_PHASE: Active; Manufacturer: TDK Electronics; Manufacturer Part Num: C1005X7R1E104M; Price: 0; RoHS Compliant: RoHS Compliant
C38 C40 C42 C45-C48 C59 C909 C943 C944 = CAP: CAP - 0.1UF 0402 25V X7R; Item Num: P03-17618R; Manufacturer: TDK Electronics; Manufacturer Part Num: C1005X7R1E104M; RoHS Compliant: RoHS Compliant
J1 = HEADER_30X2_0: 60 PIN HIGH SPEED GROUND PLANE HEARDER; Item Num: P23-38641R; Manufacturer: Samtec
J2 J10 J11 = HEADER,_1x3-PIN: CONN HEADER 3 POS 2.54MM, THROUGH HOLE; Item Num: P23-38703R; Manufacturer: Wurth Electronics; Manufacturer Part Num: 61300311121
R1 R668 = RESISTOR: RES ZERO OHM 1/16W 5% 0402 SMD; Item Num: P02-14020R; Manufacturer: Panasonic; Manufacturer Part Num: ERJ-2GE0R00X; RoHS Compliant: RoHS Compliant
R2 R4 R7 R16 R20 R23-R32 R34 R35 R675 R686-R688 R5256 R5262 R5265 R5316 = RESISTOR: RES,4.70K OHMS,1.0%,1/16W,0402; Item Num: P02-11384R; LIFECYCLE_PHASE: Active; Manufacturer: Vishay; Manufacturer Part Num: CRCW04024K70FKED; RoHS Compliant: RoHS Compliant
R681 R682 = RESISTOR: RES ZERO OHM 1/16W 5% 0402 SMD; Item Num: P02-14020R; Manufacturer: Panasonic; Manufacturer Part Num: ERJ-2GE0R00X; Price: 0; RoHS Compliant: RoHS Compliant
R698 R5257 R5259 R5269 R5275 R5310-R5312 = RESISTOR: RES,1.00KOHMS,1.0%,1/16W,0402; Item Num: P02-11372R; Manufacturer: Panasonic; Manufacturer Part Num: ERJ-2RKF1001X; Num Pins: 2; RoHS Compliant: RoHS Compliant
R6 R9-R13 R19 R5276-R5278 R5289 R5300-R5309 = RESISTOR: RES 33 OHM 1/16W 5% 0402 SMD; Item Num: P02-14029R; LIFECYCLE_PHASE: Active; Manufacturer: Panasonic; Manufacturer Part Num: ERJ-2GEJ330X; RoHS Compliant: RoHS Compliant
U14 U68 U69 = SN74AUP1G17DCK: IC - LOW-POWER SINGLE SCHMITT-TRIGGER BUFFER 0.8 V TO 3.6 V VCC; Item Num: P01-18134R; Manufacturer: Texas Instruments; Manufacturer Part Num: SN74AUP1G17DCKR; Part Number: P01-AUP1G17
C5-C8 C44 = CAP: CAP - CER, 10NF, 50V, +/-10%, X7R, 0402 SMD; Item Num: P03-16318R; Manufacturer: Murata; Manufacturer Part Num: GRM155R71H103KA88D; Price: 0; RoHS Compliant: RoHS Compliant
C11 C15 C18 C23 C26 C29 C914 C915 C928 = CAP: CAP 22UF CER 20% 6.3VDC X5R 0603 SMT; Item Num: P03-17794R; Manufacturer: Murata; Manufacturer Part Num: GRM188R60J226MEA0; Part Number: P03-17794R; Tolerance: +/-20%; Voltage: 6.3V
C28 = CAP: CAP, CERAMIC, 2.2UF, 10%, 10VDC, X5R, 0603; Item Num: P03-15213R; LIFECYCLE_PHASE: Active; Manufacturer: Murata; Manufacturer Part Num: GRM188R61A225KE34x; RoHS Compliant: RoHS Compliant
C924 C927 C954 C955 = CAP: SMD/SMT 10uF 10% 16Volts  0805; Item Num: P03-17702R; LIFECYCLE_PHASE: Active; Manufacturer: TDK Electronics; Manufacturer Part Num: C2012X5R1C106K085AC; RoHS Compliant: RoHS Compliant
C929 = CAP: CAP - CER, 1NF, 10%, 50V, X7R, 0402; Item Num: P03-15174R; LIFECYCLE_PHASE: Active; Manufacturer: Murata; Manufacturer Part Num: GRM155R71H102KA01D; Price: 0; RoHS Compliant: RoHS Compliant
C930 = CAP: CAP - CER, 120PF, 50V, 5%, C0G, 0402; Item Num: P03-15872R; LIFECYCLE_PHASE: Active; Manufacturer: Murata; Manufacturer Part Num: GRM1555C1H121JA01D; Price: 0; RoHS Compliant: RoHS Compliant
C940 C942 = CAP: CAP CER 1000PF 3KV X7R 1808; Item Num: P03-17908R; Manufacturer: Yageo; Manufacturer Part Num: CC1808KKX7REBB102; Num Pins: 2; RoHS Compliant: RoHS Compliant
J3 = ENET_L829-1J1T-43_2: CONN - RJ45 SINGLE PORT, 1000BASE-T GIGABIT ETHERNET MAGJACK 1 X 1 WITHLEDS, LOW PROFILE; Item Num: P23-38514R; Manufacturer: Bel Stewart Connector; Manufacturer Part Num: L829-1J1T-43; RoHS Compliant: RoHS Compliant
L1-L5 = IND_Ferrite_0603_3A_30_Ohms
L7 L8 = BEAD_FERRITE_SM: IND - SMD EMI FILTERS/CHIP FERRITE BEAD, 220-OHM @ 100MHZ, 0.35-OHM DCR, 0402; Item Num: P04-17068R; Manufacturer: Wurth Elektronik; RoHS Compliant: RoHS Compliant
L6 L10 L11 = BEAD_FERRITE_SM: IND - SMD EMI FILTERS/CHIP FERRITE BEAD, 220-OHM @ 100MHZ, 0.35-OHM DCR, 0402; Item Num: P04-17068R; Manufacturer: Wurth Elektronik; Num Pins: 2; RoHS Compliant: RoHS Compliant
Q1-Q7 = NMOS_3Pin: IC, MOSFET, N-CHANNEL, 20V; DCR: 0.3; Item Num: P18-31002R; Manufacturer: Fairchild Semiconductor; Voltage: 20V
R8 R14 = RESISTOR: RES, 220 OHMS, 5%, 1/16W, 0402; Item Num: P02-14107R; Manufacturer: Panasonic; Manufacturer Part Num: ERJ-2GEJ221X; Price: 0; RoHS Compliant: RoHS Compliant
R15 = RESISTOR: RES-SMD 1/16watt 12.1Kohms 1% 0402; Item Num: P02-17669R; Manufacturer: Vishay; Manufacturer Part Num: CRCW040212K1FKED; Price: 0
R17 R21 R33 R36 = RESISTOR: RES,4.70K OHMS,1.0%,1/16W,0402; Item Num: P02-11384R; LIFECYCLE_PHASE: Active; Manufacturer: Vishay; Manufacturer Part Num: CRCW04024K70FKED
R18 R83 R89-R91 R102-R105 R671 R5258 R5279-R5287 R5313 = RESISTOR: RES,10.0K OHMS,1.0%,1/16W, 0402; Item Num: P02-11364R; Manufacturer: Panasonic; Manufacturer Part Num: ERJ-2RKF1002X; Price: 0; RoHS Compliant: RoHS Compliant
R39 = RESISTOR: RES - 1.87K OHMS, 1.0%, 1/16W, 0402; Item Num: P02-16414R; Manufacturer: Vishay; Manufacturer Part Num: CRCW04021K87FKxx; RoHS Compliant: RoHS Compliant
R699 = R: RES - 2.61K OHM, 1%,1/10W, 0402 SMD; Item Num: P02-16710R; Manufacturer: Panasonic; Manufacturer Part Num: ERJ-2RKF2611x; Price: 0; RoHS Compliant: RoHS Compliant
R5266 R5268 = RESISTOR: RES SMD 1M OHM 1% 1/4W 1206; Item Num: P02-17885R; Manufacturer: PANASONIC ELECTRONIC COMPONENTS; Manufacturer Part Num: ERJ-2RKF1004X; RoHS Compliant: RoHS Compliant
U1 = KSZ9031RN_4: IC- PHY 1-CH 10MBPS/100MBPS/1GBPS 48-PIN QFN; Item Num: P01-17926R; Manufacturer: Micrel Semiconductor; Manufacturer Part Num: KSZ9031RNXCA; RoHS Compliant: RoHS Compliant
U62 = EY1501DI-ADJ: IC - EY1501DI-ADJ HIGH PERFORMANCE 1A LDO; Item Num: P01-18061R; Manufacturer: Altera Corporation
Y2 = OSC_ALT: OSC - CRYSTAL OSC. LVCMOS/LVTTL 25.000 MHZ OUTPUT SMT +/-50PPM; Item Num: P13-26150R; Manufacturer: ECS, Inc.; Manufacturer Part Num: ECS-3953C-250-B
C36 C37 = Cap_39PF_5%_50V_0402
C39 C41 C76 = CAP: CAP, CERAMIC, 2.2UF, 10%, 10VDC, X5R, 0603; Item Num: P03-15213R; Manufacturer: Murata; Manufacturer Part Num: GRM188R61A225KE34x; RoHS Compliant: RoHS Compliant
D1-D5 = LED_WURTH: LED - BRIGHT GREEN, VF=2V, IF=0.03A, 0603; Item Num: P09-21344R; LIFECYCLE_PHASE: Active; Manufacturer: Wurth Electroniks; Manufacturer Part Num: 150060VS75000; Num Pins: 2; RoHS Compliant: RoHS Compliant
J7 = USB_MINI_B_SMT: VERTICAL MINI USB 2.0 TYPE B 5 CONTACTS; Item Num: P23-38804R; Manufacturer: Würth Elektronik; Manufacturer Part Num: 651 005 136 421
J9 = CON2: 2X1 .100" CENTER HEADER; Item Num: P23-38493R; Manufacturer: Wurth Elektroniks; Manufacturer Part Num: 613 002 111 21; Num Pins: 2; Price: 0; RoHS Compliant: RoHS Compliant
R42 R46 R52-R60 R62 R64-R69 R72 R74 R77 R79 = RESISTOR: RES ZERO OHM 1/16W 5% 0402 SMD; Item Num: P02-14020R; Manufacturer: Panasonic; Manufacturer Part Num: ERJ-2GE0R00X; Num Pins: 2; RoHS Compliant: RoHS Compliant
R48 R86-R88 = RESISTOR: RES, 220 OHMS, 5%, 1/16W, 0402; Item Num: P02-14107R; Manufacturer: Panasonic; Manufacturer Part Num: ERJ-2GEJ221X; Num Pins: 2; Price: 0; RoHS Compliant: RoHS Compliant
R49 = RESISTOR: RES, 220 OHMS, 5%, 1/16W, 0402; Item Num: P02-14107R; Manufacturer: Panasonic; Manufacturer Part Num: ERJ-2GEJ221X; Num Pins: 2; Part Class: Resistors; Price: 0; RoHS Compliant: RoHS Compliant
R50 = RESISTOR: RES,10.0K OHMS,1.0%,1/16W, 0402; Item Num: P02-11364R; Manufacturer: Panasonic; Manufacturer Part Num: ERJ-2RKF1002X; Num Pins: 2; Price: 0; RoHS Compliant: RoHS Compliant
R5270 R5288 R5314 R5315 = RESISTOR: RES ZERO OHM 1/16W 5% 0402 SMD; Item Num: P02-14020R; Manufacturer: Panasonic; Manufacturer Part Num: ERJ-2GE0R00X; Num Pins: 2; Price: 0; RoHS Compliant: RoHS Compliant
R5271 = RESISTOR: RES,4.70K OHMS,1.0%,1/16W,0402; Item Num: P02-11384R; Manufacturer: Vishay; Manufacturer Part Num: CRCW04024K70FKED; Num Pins: 2; Part Class: Resistors; RoHS Compliant: RoHS Compliant
U5 = FT232R_2: IC - FTDI USB TO SERIAL UART INTERFACE, 32QFN; Item Num: P01-17819R; Manufacturer: FTDI; Manufacturer Part Num: FT232RQ-REEL; Num Pins: 32; RoHS Compliant: RoHS Compliant
U6 = TPD4S012DRYR: DIODE - HIGH SPEED, OTG, CHARGER USB ESD SOLUTION, 4CH, DRY; Item Num: P08-20820R; Manufacturer: Texas Instruments; Num Pins: 6; RoHS Compliant: RoHS Compliant
U63 = SN74AUP1G126DCK: IC - LOW-POWER SINGLE BUS BUFFER GATE WITH 3-STATE OUTPUT 3.6-V I/O TOLERANT; Item Num: P01-18133R; Manufacturer: Texas Instruments; Manufacturer Part Num: SN74AUP1G126DCKT
U64 U65 = SN74AUP1G17DCK: IC - SINGLE SCHMITT-TRIGGER BUFFER, 1.8/2.5/3.3V in, 3.3V CMOS out; Item Num: P01-18132R; Manufacturer: Texas Instruments
C49 = CAP: CAP 1UF CER 10% 50VDC X5R 0603 SMT; AGILE_LINK: http://sj-agile9app/Agile/PLMServlet?action=OpenEmailObject&classid=10000&objid=256999866; Item Num: P03-17790R; LIFECYCLE_PHASE: Active; Lead Free Status: Lead Free; MFR_LIFECYCLE: Active; Manufacturer: Murata; Manufacturer Part Num: GRM188R61H105KAAL; Num Pins: 2; PART_SUBCLASS: CAPACITORS; RoHS Compliant: RoHS Compliant
C51 C53 C957 = CAP: CAP, CERAMIC, 2.2UF, 10%, 10VDC, X5R, 0603; AGILE_LINK: http://sj-agile9app/Agile/PLMServlet?action=OpenEmailObject&classid=10000&objid=256999866; Item Num: P03-15213R; LIFECYCLE_PHASE: Active; Lead Free Status: Lead Free; MFR_LIFECYCLE: Active; Manufacturer: Murata; Manufacturer Part Num: GRM188R61A225KE34x; Num Pins: 2; PART_SUBCLASS: CAPACITORS; RATED_VOLTAGE: 10V; RoHS Compliant: RoHS Compliant; Supplier Part Num: 490-1545-1-ND; TOLERANCE: +/-10%
C52 C54 C958-C960 = CAP: CAP - CERAMIC, 0.22UF, 10V, X5R, 10%, 0402; AGILE_LINK: http://sj-agile9app/Agile/PLMServlet?action=OpenEmailObject&classid=10000&objid=257560276; Item Num: P03-15149R; LIFECYCLE_PHASE: Active; Lead Free Status: Not Lead Free; MFR_LIFECYCLE: Active; Manufacturer: Murata; Manufacturer Part Num: GRM155R61A224KE19D; Num Pins: 2; PART_SUBCLASS: CAPACITORS; RATED_VOLTAGE: 10V; RoHS Compliant: RoHS Compliant; TOLERANCE: +/-10%
U7 = MT29F8G16ABBCAH4-IT_1: 8Gb X16 1.8V NAND FLASH MEMORY; Item Num: P01-18111R
U8 = MTFC8GAKAJCN-4M_IT: IC - eMMC,8GB,VFBGA-153; Item Num: P01-18101R; Manufacturer: Micron
C70 C956 = CAP: CAP - 0.1UF 0402 25V X7R; Item Num: P03-17618R; Manufacturer: TDK Electronics; Manufacturer Part Num: C1005X7R1E104M; Tolerance: +/-20%; Voltage: 25V
S1 S2 = TS-A02SA-2-S100_0: SWITCH - PUSH BUTTON 6.0X3.5MM SND; Item Num: P23-38485R; Lead Free Status: Yes; Manufacturer: Wurth Elektroniks; Manufacturer Part Num: 434121043816; Num Pins: 2; Part Class: Switches; RoHS Compliant: Yes
Y1 = OSC_ALT: OSC - CLOCK OSCILLATOR, 25MHZ, +/-50PPM, 1.8V, SMD; Item Num: P13-27249R; Manufacturer: Silicon Labs Inc.; Manufacturer Part Num: 510KBA25M0000BAG
C900 = CAP: CAP, CERAMIC, 100PF, 0402, 5%, 50VDC, NPO; Item Num: P03-11677R; Manufacturer: Murata; Manufacturer Part Num: GRM1555C1H101JZ01D; Tolerance: +/-5%; Voltage: 50V
C917 = CAP: CAP - CERAMIC, 10UF, 10%, X5R, 25V, 1206; Item Num: P03-15063R; Manufacturer: Murata; Manufacturer Part Num: GRM31CR61E106KA12; RoHS Compliant: RoHS Compliant
C922 = CAP: CAP - CER, 10NF, 50V, +/-10%, X7R, 0402 SMD; Dielectric: X5R; Item Num: P03-16318R; Manufacturer: Murata; Manufacturer Part Num: GRM155R71H103KA88D; Price: 0.07; RoHS Compliant: RoHS Compliant
C949 = CAP: CAP - CER 47UF 10V 20% X5R 1206; Dielectric: X5R; Item Num: P03-17644R; Manufacturer: TDK Electronics; Manufacturer Part Num: C3216X5R1A476M160AB; RATED_VOLTAGE: 6.3v; RoHS Compliant: Yes; Tolerance: 20%; Working Voltage: 6.3V
R456 = RESISTOR_0402: RES 13.3K OHM 1/16W 1.0% 0402 SMD; Manufacturer: Vishay; Manufacturer Part Num: CRCW040213K3FKED; item Num: P02-14487R
R667 = Resistor,_0402: RES 324K OHM 1/10W 1% 0402 SMD; Item Num: P02-16733R; Manufacturer: Panasonic; Manufacturer Part Num: ERJ-2RKF3243X
U15 = LTM4623EV#PBF: REG - 4V to 20VIN, 3A Step-Down DC/DC ?Module Regulator, BGA25; Item Num: P05-18787R; Manufacturer: Linear Technology

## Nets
GND: C1.2 C2.1 C3.2 C4.1 C5.2 C6.2 C7.2 C8.2 C11.2 C13.1 C15.2 C17.1 C18.2 C20.1 C23.2 C25.1 C26.2 C28.2 C29.2 C31.1 C36.2 C37.2 C38.1 C39.2 C40.1 C41.2 C42.1 C43.2 C44.1 C45.1 C46.1 C47.1 C48.1 C49.2 C50.1 C51.2 C52.2 C53.2 C54.2 C55.1 C56.1 C59.2 C70.2 C76.2 C909.2 C914.2 C915.2 C917.2 C922.2 C924.2 C925.1 C927.2 C928.2 C929.1 C931.1 C932.1 C933.1 C934.1 C935.1 C936.1 C937.1 C938.1 C939.1 C940.1 C942.1 C943.2 C944.2 C949.1 C953.1 C954.2 C955.2 C956.2 C957.2 C958.2 C959.2 C960.2 C961.2 C962.2 C964.1 C965.2 J1.61 J1.62 J1.63 J1.64 J2.3 J7.5(SHIELD) J9.2 J10.3 Q1.2(SOURCE) Q2.2(SOURCE) Q3.2(SOURCE) Q4.2(SOURCE) Q5.2(SOURCE) Q6.2(SOURCE) Q7.2(SOURCE) R1.2 R15.2 R17.2 R21.2 R24.2 R26.2 R28.2 R30.2 R32.2 R34.2 R36.2 R39.1 R46.2 R667.1 R668.1 R698.1 R5257.2 R5266.2 R5268.2 R5275.1 R5287.2 S1.1 S2.1 U1.29(VSS) U1.49(P_GND) U5.4(GND1) U5.17(GND2) U5.20(GND3) U5.24(AGND) U5.26(TEST) U5.33(EPAD_GND) U6.4(GND) U7.C5(Vss1) U7.F7(Vss2) U7.K3(Vss3) U7.K8(Vss4) U8.A6(VSS1) U8.C4(VSSQ1) U8.D4(NC33) U8.E7(VSS2) U8.G5(VSS3) U8.H10(VSS4) U8.J5(VSS5) U8.K8(VSS6) U8.N1(NC90) U8.N2(VSSQ2) U8.N5(VSSQ3) U8.P4(VSSQ4) U8.P6(VSSQ5) U14.3(GND) U15.B2(PHMODE) U15.B3(GND_1) U15.B4(SGND) U15.C3(GND_2) U15.D3(GND_3) U15.D4(GND_4) U15.E3(GND_5) U62.5(GND) U62.11(EPAD) U63.3(GND) U64.3(GND) U65.3(GND) U68.3(GND) U69.3(GND) Y1.2(GND) Y2.2(GND)
VCC_3.3V: C51.1 C52.1 C76.1 C900.1 C924.1 C928.1 C949.2 C958.1 L1.1 L7.1 R8.1 R14.1 R86.1 R87.1 R88.1 R5262.2 U8.E6(VCC1) U8.F5(VCC2) U8.J10(VCC3) U8.K9(VCC4) U15.C1(VOUT_1) U15.D1(VOUT_2) U15.D2(VOUT_3) U15.E1(VOUT_4) U15.E2(VOUT_5) U62.9(VIN2) U62.10(VIN1)
VCC_12V: C3.1 C4.2 C917.1 C962.1 J1.1 J1.60 U15.C5(SVIN) U15.D5(VIN_1) U15.E5(VIN_2)
VCCIO_HPS: C1.1 C2.2 C45.2 C46.2 C47.2 C48.2 C53.1 C54.1 C70.1 C909.1 C944.1 C954.1 C956.1 C957.1 C959.1 C960.1 C961.1 J1.2 J1.59 L2.1 L8.1 R2.1 R4.1 R7.1 R83.2 R89.2 R90.2 R102.2 R103.2 R104.2 R105.2 R675.1 R686.1 R687.1 R688.1 R5256.1 R5258.2 R5279.2 R5280.2 R5281.2 R5282.2 R5283.2 R5284.2 R5285.2 R5286.2 R5310.1 R5311.1 R5312.1 R5313.1 R5316.1 U7.D3(Vcc1) U7.G4(Vcc2) U7.H8(Vcc3) U7.J6(Vcc4) U8.C6(VCCQ1) U8.M4(VCCQ2) U8.N4(VCCQ3) U8.P3(VCCQ4) U8.P5(VCCQ5) U14.5(VCC) U63.5(VCC) U68.5(VCC) U69.5(VCC)
VDDIM: C49.1 C50.2 U8.C1(NC19) U8.C2(VDDIM)
ACTIVITY_LED: J3.13(YK) L10.2
CARD_PRSTn: J1.52 R1.1
CLK125_NDO_LED_MODE: R35.2 R36.1 U1.41(CLK125_NDO_LED_MODE)
CT0: C5.1 J3.12(CT0)
CT1: C6.1 J3.6(CT1)
CT2: C7.1 J3.1(CT2)
CT3: C8.1 J3.7(CT3)
DC_PGOOD: J1.54 R671.1 U15.C2(PGOOD)
DIP_1: J9.1 R5269.2 R5287.1 U63.1(OE)
E_RX_CLK: R6.1 R33.2 R34.1 U1.35(RX_CLK_PHYAD2)
E_RX_DV: R9.1 R31.2 R32.1 U1.33(RX_DV_CLK125_EN)
E_RXD0: R10.1 R29.2 R30.1 U1.32(RXD0_MODE0)
E_RXD1: R11.1 R27.2 R28.1 U1.31(RXD1_MODE1)
E_RXD2: R12.1 R25.2 R26.1 U1.28(RXD2_MODE2)
E_RXD3: R13.1 R23.2 R24.1 U1.27(RXD3_MODE3)
EMMC_CLK: R53.2 U8.M6(CLK) U8.N7(NC93) U8.P7(NC103)
EMMC_CMD: R54.2 R83.1 R5309.1
EMMC_COMMAND: R5309.2 U8.L1(NC73) U8.L2(NC74) U8.L3(NC75) U8.M5(CMD)
EMMC_D0: R69.2 R5279.1 R5301.1
EMMC_D1: R74.2 R5281.1 R5302.1
EMMC_D2: R67.2 R5280.1 R5303.1
EMMC_D3: R57.2 R5282.1 R5304.1
EMMC_D4: R59.2 R5283.1 R5305.1
EMMC_D5: R79.2 R5284.1 R5306.1
EMMC_D6: R62.2 R5285.1 R5307.1
EMMC_D7: R65.2 R5286.1 R5308.1
EMMC_DAT0: R5301.2 U8.A3(DAT0)
EMMC_DAT1: R5302.2 U8.A4(DAT1)
EMMC_DAT2: R5303.2 U8.A5(DAT2)
EMMC_DAT3: R5304.2 U8.A1(NC1) U8.B2(DAT3)
EMMC_DAT4: R5305.2 U8.A2(NC2) U8.B3(DAT4)
EMMC_DAT5: R5306.2 U8.B4(DAT5) U8.C3(NC20) U8.D1(NC30) U8.D2(NC31)
EMMC_DAT6: R5307.2 U8.B5(DAT6) U8.C5(NC21)
EMMC_DAT7: R5308.2 U8.A8(NC3) U8.B6(DAT7) U8.B7(NC11)
EMMC_RST_N: J10.2 R5314.2 U8.J1(NC61) U8.J2(NC62) U8.J3(NC63) U8.K5(RST_N)
EMMC_RSTn: J10.1 R5278.2 R5314.1
ENET_1.2V_AVDDL: C23.1 C25.2 C931.2 L4.2 U1.4(AVDDL) U1.9(AVDDL)
ENET_1.2V_AVDLL_PLL: C18.1 C20.2 L3.2 U1.44(AVDDL_PLL)
ENET_1.2V_DVDDL: C29.1 C31.2 C932.2 C933.2 C934.2 C935.2 C936.2 L5.2 U1.14(DVDDL) U1.18(DVDDL) U1.23(DVDDL) U1.26(DVDDL) U1.30(DVDDL) U1.39(DVDDL)
ENET_1.8V_DVDDH: C15.1 C17.2 C938.2 C939.2 L2.2 R16.1 R20.1 R23.1 R25.1 R27.1 R29.1 R31.1 R33.1 R35.1 U1.16(DVDDH) U1.34(DVDDH) U1.40(DVDDH)
ENET_3.3V_AVDDH: C11.1 C13.2 C937.2 L1.2 U1.1(AVDDH) U1.12(AVDDH)
ENET_GTX_CLK: J1.39 U1.24(GTX_CLK)
ENET_INTn: J1.27 R7.2 U1.38(INT_N/PME_N2)
ENET_LED1: Q6.1(GATE) R20.2 R21.1 U1.17(LED1_PHYAD0/PME_N1)
ENET_LED2: Q4.1(GATE) R16.2 R17.1 U1.15(LED2_PHYAD1)
ENET_MDC: J1.36 R2.2 U1.36(MDC)
ENET_MDIO: J1.35 R4.2 U1.37(MDIO)
ENET_RSET: R15.1 U1.48(ISET)
ENET_RSTn: R5276.2 U1.42(RESET_N)
ENET_RX_CLK: J1.41 R6.2
ENET_RX_DV: J1.42 R9.2
ENET_RXD0: J1.45 R10.2
ENET_RXD1: J1.46 R11.2
ENET_RXD2: J1.49 R12.2
ENET_RXD3: J1.50 R13.2
ENET_TX_EN: J1.40 U1.25(TX_EN)
ENET_TXD0: J1.43 U1.19(TXD0)
ENET_TXD1: J1.44 U1.20(TXD1)
ENET_TXD2: J1.47 U1.21(TXD2)
ENET_TXD3: J1.48 U1.22(TXD3)
ENET_VDD1.2V: C26.1 C28.1 C930.2 L3.1 L4.1 L5.1 R699.1 R5265.2 U62.1(VOUT1) U62.2(VOUT2)
ENET_XI: R19.2 U1.46(XI)
FT232R_3V3OUT: C38.2 C39.1 R42.1 U5.16(3V3OUT)
FT232R_RXD: U5.2(RXD) U65.4(Y)
FT232R_TXD: U5.30(TXD) U63.2(A)
FT232R_VCCIO: C40.2 C41.1 C59.1 C914.1 C943.1 D1.A(ANODE) D2.A(ANODE) R42.2 R50.2 R5269.1 R5271.1 U5.1(VCCIO) U64.5(VCC) U65.5(VCC)
GPIO_RESERVED0: J1.56 R681.1
GPIO_RESERVED1: J1.57 R682.1
HPS_LED0: J1.28 Q1.1(GATE) R681.2
HPS_LED1: J1.37 Q3.1(GATE) R682.2
HPS_LED2: J1.38 Q2.1(GATE)
HPS_OSC_CLK: J1.18 R5289.2
HPS_OSC_CLK_1.8V: C953.2 C955.1 L8.2 R91.1 Y1.4(VCC)
HPS_PB0: J1.31 U14.4(Y)
HPS_PB1: J1.32 U69.4(Y)
HPS_RESETn: J1.53 R675.2 U68.2(A)
I2C1_SCL: J1.34 J2.1 R5256.2
I2C1_SDA: J1.33 J2.2 R686.2
LDO_O: U1.43(LDO_O)
LINK_LED: J3.17(GK) L11.2
LT_INTVCC: R671.2 R5259.1 U15.E4(INTVCC)
MDI_HPS_N0: J3.10(TD0_N) U1.3(TXRXM_A)
MDI_HPS_N1: J3.5(TD1_N) U1.6(TXRXM_B)
MDI_HPS_N2: J3.2(TD2_N) U1.8(TXRXM_C)
MDI_HPS_N3: J3.9(TD3_N) U1.11(TXRXM_D)
MDI_HPS_P0: J3.11(TD0_P) U1.2(TXRXP_A)
MDI_HPS_P1: J3.4(TD1_P) U1.5(TXRXP_B)
MDI_HPS_P2: J3.3(TD2_P) U1.7(TXRXP_C)
MDI_HPS_P3: J3.8(TD3_P) U1.10(TXRXP_D)
MINI_USB_PGND: C940.2 J7.6(SHIELD2) J7.7(SHIELD3) R5266.1
NAND_ADQ0: R52.2 U7.H4(IO0)
NAND_ADQ0_EMMC_CLK: J1.3 R52.1 R53.1
NAND_ADQ1: R55.2 U7.J4(IO1)
NAND_ADQ1_EMMC_CMD: J1.4 R54.1 R55.1
NAND_ADQ2: R56.2 U7.K4(IO2)
NAND_ADQ2_EMMC_D3: J1.8 R56.1 R57.1
NAND_ADQ3: R58.2 U7.K5(IO3)
NAND_ADQ3_EMMC_D4: J1.9 R58.1 R59.1
NAND_ADQ4: R60.2 U7.K6(IO4)
NAND_ADQ4_EMMC_D6: J1.11 R60.1 R62.1
NAND_ADQ5: R64.2 U7.J7(IO5)
NAND_ADQ5_EMMC_D7: J1.12 R64.1 R65.1
NAND_ADQ6: J1.13 U7.K7(IO6)
NAND_ADQ7: J1.14 U7.J8(IO7)
NAND_ADQ8: J1.19 U7.H3(IO8)
NAND_ADQ9: J1.20 U7.J3(IO9)
NAND_ADQ10: J1.21 U7.H5(IO10)
NAND_ADQ11: J1.22 U7.J5(IO11)
NAND_ADQ12: J1.23 U7.H6(IO12)
NAND_ADQ13: J1.24 U7.G6(IO13)
NAND_ADQ14: J1.25 U7.H7(IO14)
NAND_ADQ15: J1.26 U7.G7(IO15)
NAND_ALE: J1.15 U7.C4(ALE)
NAND_CE_N: J11.2 R5315.2 U7.C6(CE#)
NAND_CEn: J1.17 J11.1 R103.1 R5315.1
NAND_CLE: R77.2 U7.D5(CLE)
NAND_CLE_EMMC_D5: J1.10 R77.1 R79.1
NAND_RBn: J1.16 R5258.1 U7.C8(R/B#)
NAND_REn: R72.2 R104.1 U7.D4(RE#)
NAND_REn_EMMC_D1: J1.6 R72.1 R74.1
NAND_WEn: R68.2 R105.1 U7.C7(WE#)
NAND_WEn_EMMC_D0: J1.5 R68.1 R69.1
NAND_WPn: R66.2 R102.1 U7.C3(WP#)
NAND_WPn_EMMC_D2: J1.7 R66.1 R67.1
PB_SW0: C55.2 R89.1 S1.2 U14.2(A)
PB_SW1: C56.2 R90.1 S2.2 U69.2(A)
PHY_25M_3.3V: C925.2 C927.1 L7.2 R18.1 Y2.4(VCC)
PWN_EN: J1.51 R698.2 R5316.2 U15.A3(RUN)
PWR_ENA: R50.1 U5.11(CBUS3)
RJ45_PGND: C942.2 J3.18(GND_TAB) J3.19(GND_TAB) R5268.1
UART_RESETn: R5270.2 R5271.2 U5.18(~{RESET})
UART_RSTn: R5277.2 U64.2(A)
UART_RX: J1.30 R688.2 R5288.2 R5300.1
UART_RX_LED: R49.1 U5.21(CBUS1)
UART_TX: J1.29 R687.2 R5288.1 U65.2(A)
UART_TX_LED: R48.1 U5.22(CBUS0)
USB_UART_5V: C42.2 C43.1 L6.1 U5.19(VCC) U6.6(VBUS)
USB_UART_CON_5V: C44.2 C915.1 J7.1(VBUS) L6.2
USB_UART_DM: C36.1 J7.2(D-) U5.15(USBDM) U6.1(D+)
USB_UART_DP: C37.1 J7.3(D+) U5.14(USBDP) U6.2(D-)
N134005839: J7.4(GND) R46.1
N134005899: D1.C(CATHODE) R48.2
N134005901: D2.C(CATHODE) R49.2
N134231689: D3.A(ANODE) R86.2
N134231691: D3.C(CATHODE) Q1.3(DRAIN)
N134231729: D5.A(ANODE) R88.2
N134231731: D5.C(CATHODE) Q3.3(DRAIN)
N134231769: D4.A(ANODE) R87.2
N134231771: D4.C(CATHODE) Q2.3(DRAIN)
N134232203: R91.2 Y1.1(EN)
N134232219: R5289.1 Y1.3(OUT)
N134273498: C930.1 R39.2 R699.2 U62.3(VFB)
N134273619: R5262.1 U62.7(EN)
N134273639: C929.2 U62.6(SS)
N134273687: R5265.1 U62.4(POK)
N134278396: R5270.1 U64.4(Y)
N134279761: C900.2 R456.2 U15.B1(FB)
N134279929: R5259.2 R5275.2 U15.C4(MODE)
N134279963: C922.1 U15.A2(TRACK/SS)
N134279979: R667.2 U15.A4(FREQ)
N134280029: R456.1 R668.2
N134283374: R5276.1 R5277.1 R5278.1 U68.4(Y)
N134303554: R5300.2 U63.4(Y)
N134317635: R5257.1 R5310.2 U7.G5(LOCK)
N134318194: R18.2 Y2.1(EN)
N134318932: Q4.3(DRAIN) Q5.1(GATE) R5311.2
N134318968: Q6.3(DRAIN) Q7.1(GATE) R5312.2
N134337815: J11.3 R5313.2
N134369684: R19.1 Y2.3(OUT)
N134402864: L10.1 Q7.3(DRAIN)
N134402995: L11.1 Q5.3(DRAIN)
N134403086: C965.1 J3.14(YA) R8.2
N134403345: C964.2 J3.16(GOA) R14.2

Not connected (* = marked no-connect by the designer): J1 55* 58*; J3 15(OK)*; U1 13(NC)* 45(XO)* 47(NC1)*; U5 3(~{RI})* 5(NC3)* 6(~{DSR})* 7(~{DCD})* 8(~{CTS})* 9(CBUS4)* 10(CBUS2)* 12(NC4)* 13(NC5)* 23(NC2)* 25(NC1)* 27(OSCI)* 28(OSCO)* 29(NC6)* 31(~{DTR})* 32(~{RTS})*; U6 3(ID)* 5(NC)*; U7 A1(NC1)* A2(NC2)* A9(NC3)* A10(NC4)* B1(NC5)* B9(NC6)* B10(NC7)* D6(NC8)* D7(NC9)* D8(NC10)* E3(NC11)* E4(NC12)* E5(NC13)* E6(NC14)* E7(NC15)* E8(NC29)* F3(NC16)* F4(NC17)* F5(NC18)* F6(NC19)* F8(NC20)* G3(DNU1)* G8(DNU2)* L1(NC21)* L2(NC22)* L9(NC23)* L10(NC24)* M1(NC25)* M2(NC26)* M9(NC27)* M10(NC28)*; U8 A7(RFU1)* A9(NC4)* A10(NC5)* A11(NC6)* A12(NC7)* A13(NC8)* A14(NC9)* B1(NC10)* B8(NC12)* B9(NC13)* B10(NC14)* B11(NC15)* B12(NC16)* B13(NC17)* B14(NC18)* C7(NC22)* C8(NC23)* C9(NC24)* C10(NC25)* C11(NC26)* C12(NC27)* C13(NC28)* C14(NC29)* D3(NC32)* D12(NC34)* D13(NC35)* D14(NC36)* E1(NC37)* E2(NC38)* E3(NC39)* E5(RFU2)* E8(RFU3)* E9(RFU4)* E10(RFU5)* E12(NC40)* E13(NC41)* E14(NC42)* F1(NC43)* F2(NC44)* F3(NC45)* F10(RFU6)* F12(NC46)* F13(NC47)* F14(NC48)* G1(NC49)* G2(NC50)* G3(NC51)* G10(RFU7)* G12(NC52)* G13(NC53)* G14(NC54)* H1(NC55)* H2(NC56)* H3(NC57)* H5(DS)* H12(NC58)* H13(NC59)* H14(NC60)* J12(NC64)* J13(NC65)* J14(NC66)* K1(NC67)* K2(NC68)* K3(NC69)* K6(RFU8)* K7(RFU9)* K10(RFU10)* K12(NC70)* K13(NC71)* K14(NC72)* L12(NC76)* L13(NC77)* L14(NC78)* M1(NC79)* M2(NC80)* M3(NC81)* M7(NC82)* M8(NC83)* M9(NC84)* M10(NC85)* M11(NC86)* M12(NC87)* M13(NC88)* M14(NC89)* N3(NC91)* N6(NC92)* N8(NC94)* N9(NC95)* N10(NC96)* N11(NC97)* N12(NC98)* N13(NC99)* N14(NC100)* P1(NC101)* P2(NC102)* P8(NC104)* P9(NC105)* P10(RFU11)* P11(NC106)* P12(NC107)* P13(NC108)* P14(NC109)*; U14 1(NC)*; U15 A1(COMP)* A5(CLKIN)* B5(CLKOUT)*; U62 8(NC); U64 1(NC)*; U65 1(NC)*; U68 1(NC)*; U69 1(NC)*

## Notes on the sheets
sheet 1
- NOTES:
- 1.
- Project Drawing Numbers:
       Raw PCB
       Gerber Files
       PCB Design Files
       Assembly Drawing
       Fab Drawing
       Schematic Drawing
       PCB Film
       Bill of Materials
       Schematic Design Files
       Functional Specification
       PCB Layout Guidelines
       Assembly Rework
- 100-0330633-A1
  110-0330633-A1
  120-0330633-A1
  130-0330633-A1
  140-0330633-A1
  150-0330633-A1
  160-0330633-A1
  170-0330633-A1
  180-0330633-A1
  210-0330633-A1
  220-0330633-A1
  320-0330633-A1
- Pre-Release Schematic
        DO NOT COPY
- REV
- DATE
- PAGE
- DESCRIPTION
- A
- initial schematic release
- 2.
- This board was designd for Stratix 10 SoC Development Kit.
- PAGE
- DESCRIPTION
- 1
- Title
- 2
- IO48 Connector
- 3
- RGMII Ethernet
- 4
- USB2UART
- 5
- NAND/eMMC
- 6
- PBs, LEDs
- 7
- Power
- PAGE
- DESCRIPTION
- 1
- Page Description, revision history
- 2
- FMC connector A
- 3
- FMC connector B
sheet 2
- IO48_GPIO0_NAND_ADQ0
- IO48_GPIO1_NAND_ADQ1
- IO48_GPIO2_NAND_WEn
- IO48_GPIO3_NAND_REn
- IO48_GPIO4_NAND_WPn
- IO48_GPIO5_NAND_ADQ2
- IO48_GPIO6_NAND_ADQ3
- IO48_GPIO7_NAND_CLE
- IO48_GPIO8_NAND_ADQ4
- IO48_GPIO9_NAND_ADQ5
- IO48_GPIO10_NAND_ADQ6
- IO48_GPIO12_NAND_ALE
- IO48_GPIO11_NAND_ADQ7
- IO48_GPIO13_NAND_RB
- IO48_GPIO14_NAND_CEn
- IO48_GPIO15_HPS_OSC_CLK
- IO48_GPIO16_NAND_ADQ8
- IO48_GPIO17_NAND_ADQ9
- IO48_GPIO18_NAND_ADQ10
- IO48_GPIO19_NAND_ADQ11
- IO48_GPIO20_NAND_ADQ12
- IO48_GPIO21_NAND_ADQ13
- IO48_GPIO22_NAND_ADQ14
- IO48_GPIO24_GPIO1_IO0
- IO48_GPIO23_NAND_ADQ15
- IO48_GPIO25_GPIO1_IO1
- IO48_GPIO26_UART_TX
- IO48_GPIO27_UART0_RX
- IO48_GPIO28_GPIO1_IO4
- IO48_GPIO29_GPIO1_IO5
- IO48_GPIO30_I2C1_SDA
- IO48_GPIO31_I2C1_SCL
- IO48_GPIO32_MDIO2_MDIO
- IO48_GPIO33_MDIO2_MDC
- IO48_GPIO34_GPIO1_IO10
- IO48_GPIO35_GPIO1_IO11
- IO48_GPIO36_EMAC2_TX_CLK
- IO48_GPIO38_EMAC2_RX_CLK
- IO48_GPIO37_EMAC2_TX_CTL
- IO48_GPIO39_EMAC2_RX_CTL
- IO48_GPIO40_EMAC2_TXD0
- IO48_GPIO41_EMAC2_TXD1
- IO48_GPIO42_EMAC2_RXD0
- IO48_GPIO43_EMAC2_RXD1
- IO48_GPIO44_EMAC2_TXD2
- IO48_GPIO45_EMAC2_TXD3
- IO48_GPIO46_EMAC2_RXD2
- IO48_GPIO47_EMAC2_RXD3
- MotherBoard:        QSH-030-01-C-D-A
  IO48 OOBE Card:  QTH-030-02-L-D-A
  Stack-up Height:     8mm
- Used in S10 Check out board
- I2C Header
- Reset FPGA logic externally by HPS
- Update external watchdog for HP
sheet 3
- 10/100/1000 Ethernet - HPS
- Activity (RX, TX) : Blinking
- No Activity:  OFF
- NAME
- Pin
- Value
- Description
- PHYAD2
- 35
- 1
- ID = b"100"
- PHYAD1
- 15
- 0
- On-Chip Termination Resistors for the Differential Pairs
- PHYAD0
- 17
- 0
- RGMII
  (10/100/1000 half-/full-duplex)
- MODE3
- 27
- 1
- MODE2
- 28
- 1
- MODE1
- 31
- 1
- MODE0
- 32
- 1
- ClK125_EN
- 33
- 0
- No clockoutput from pin41
- single led
  mode
- Link OFF
- LED_MODE
- 41
- 1
- Link ON
- Activity
- Link
- Use AVDDH supply for the crystal/clock pins (XI, XO)
- BOOT-STRAPS
- Place near KSZ9031RN PHY
- Ethernet 1.2V LDO
- 250mA Max.
- PUS: AVDDH/DVDDH before 1.2V core
sheet 4
- USB-UART Port
- OE=L
  A=X (Floating input allowed)
  Y=Z
- Debugging Loopback
  Pop R5288, short J9
- WE 651005136421
sheet 5
- LED, PushButton, CLK
- Notes:
  LED is ON when HPS_LEDx is high
  LED is OFF when HPS_LEDx is low
- 25MHz HPS CLK
sheet 6
- 12V -> 3.3V
- 3.3V/1A (Max.)
- 25V
- VCC - Continuous Mode
  GND - Discontinous Mode
- soft-start time=3ms
sheet 7
- NAND/eMMC
- Socketable: Ironwood SG-BGA-6367
- When LOCK is HIGH during power-up, the BLOCK LOCK function is enabled.
  When LOCK is LOW during power-up, the BLOCK LOCK function is disabled.
- When Nand Active
  Short J10 pin2 and pin3
  Short J11 pin2 and pin1
- When EMMC Active
  Short J10 pin2 and pin1
  Short J11 pin2 and pin3
- DS is used in HS400 mode
